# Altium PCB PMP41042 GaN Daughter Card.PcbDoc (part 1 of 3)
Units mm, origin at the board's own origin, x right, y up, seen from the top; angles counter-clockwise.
Board outline 43.43 x 37.33 mm, 6 copper layers (Top Layer, MidLayer1, MidLayer2, MidLayer3, MidLayer4, Bottom Layer), stack 1.844 mm thick; 57 components, 55 nets, 240 pads, 238 vias.
Unrouted connection lines stored in the file: 15.
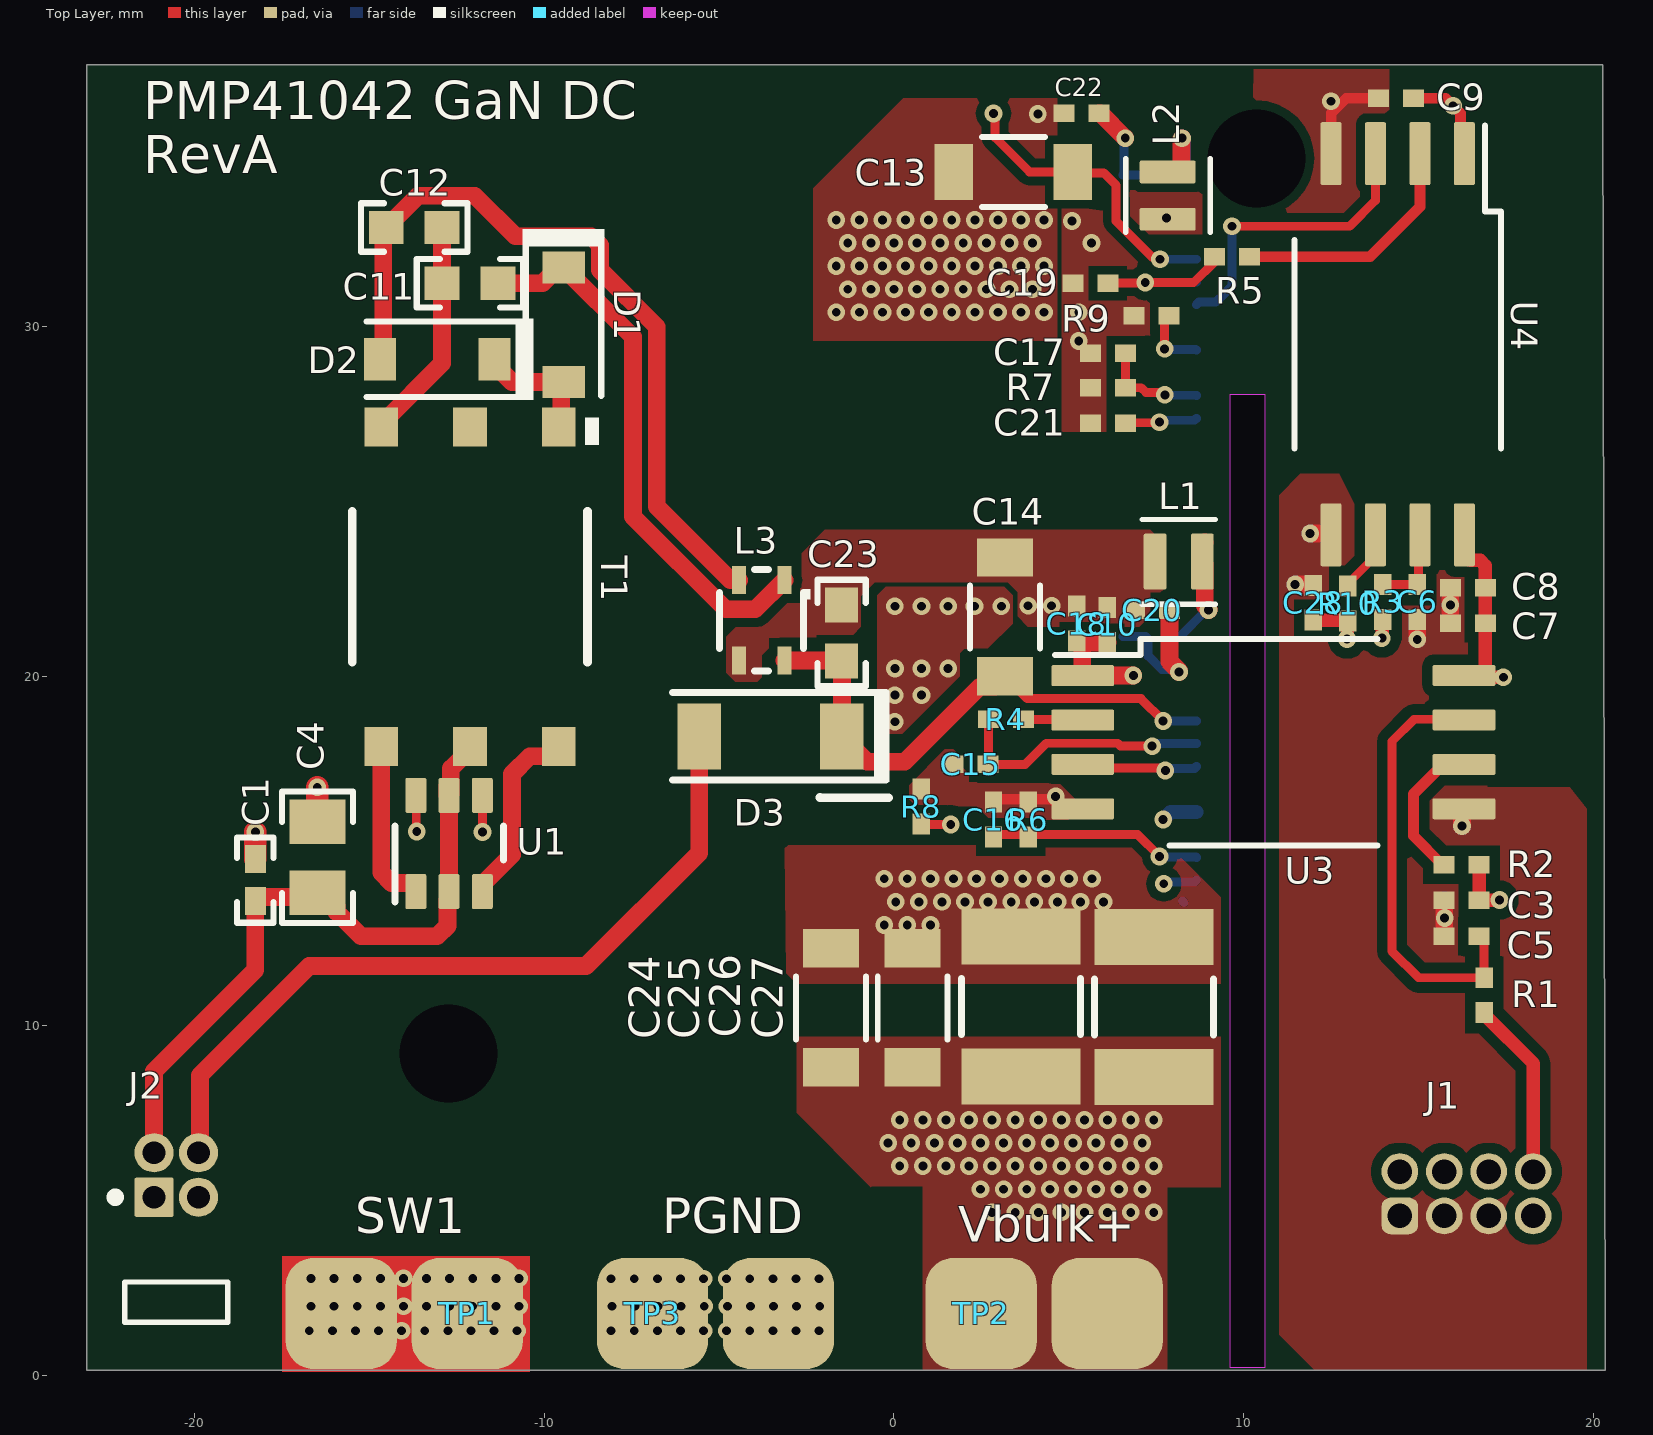
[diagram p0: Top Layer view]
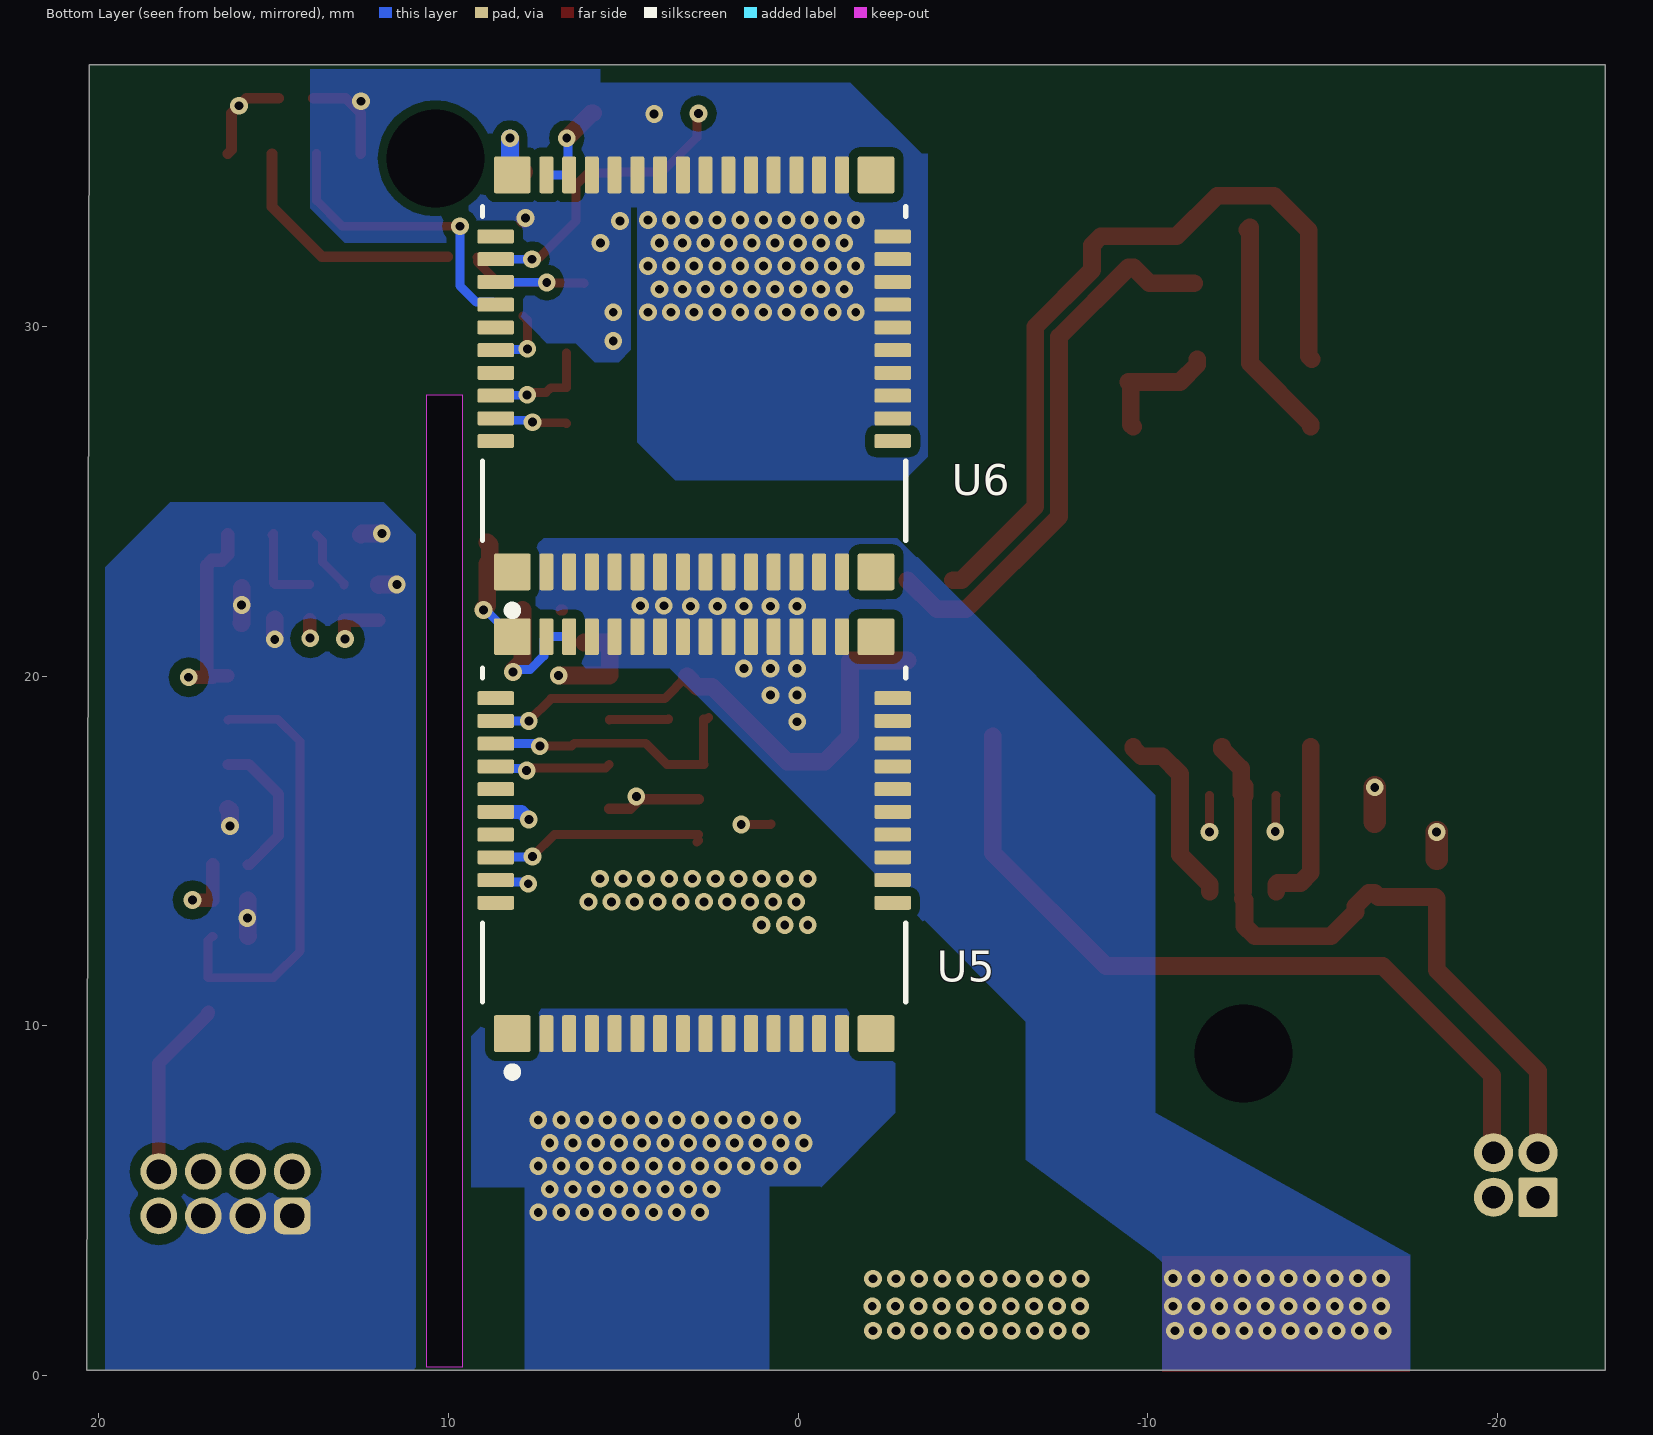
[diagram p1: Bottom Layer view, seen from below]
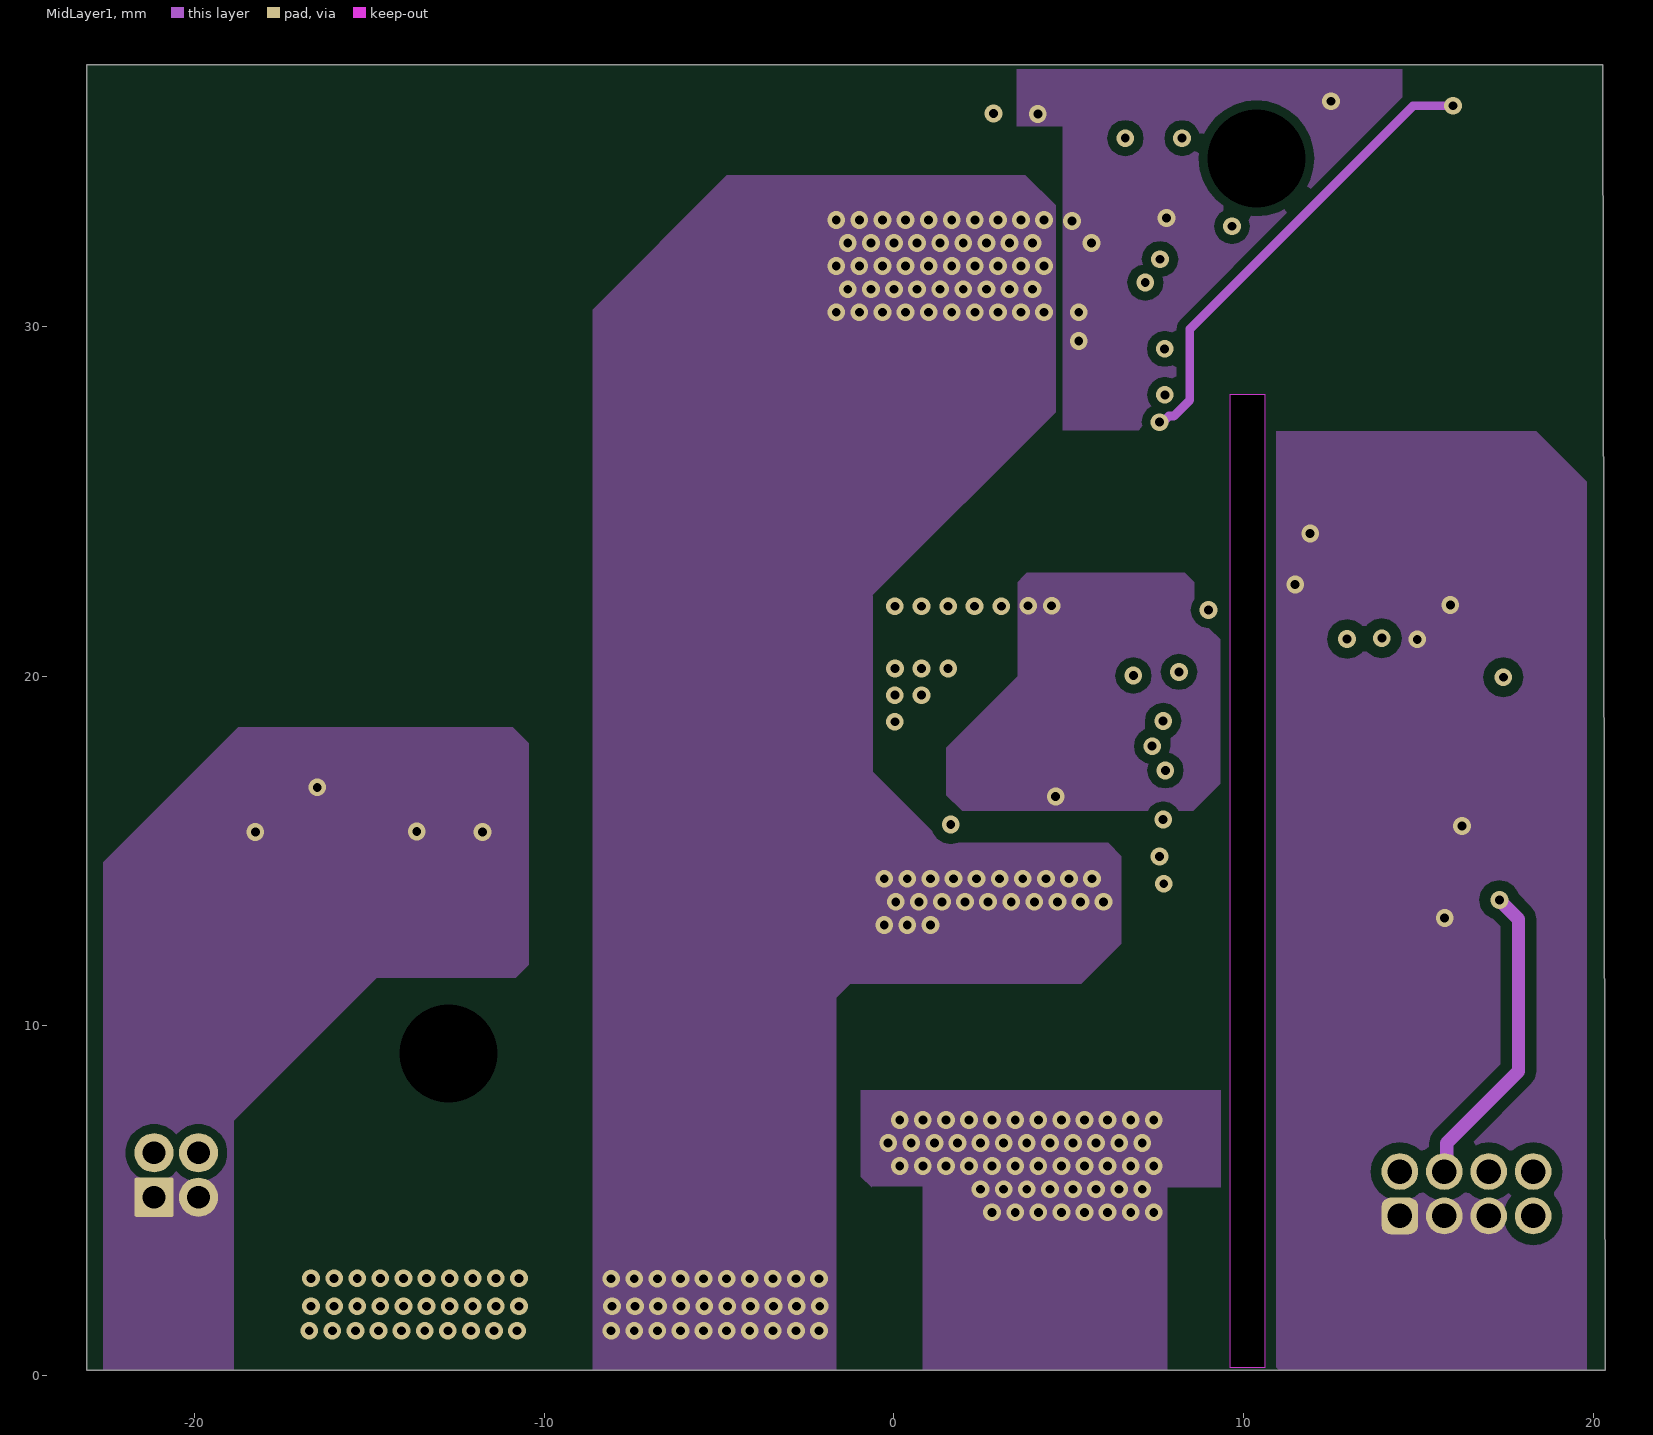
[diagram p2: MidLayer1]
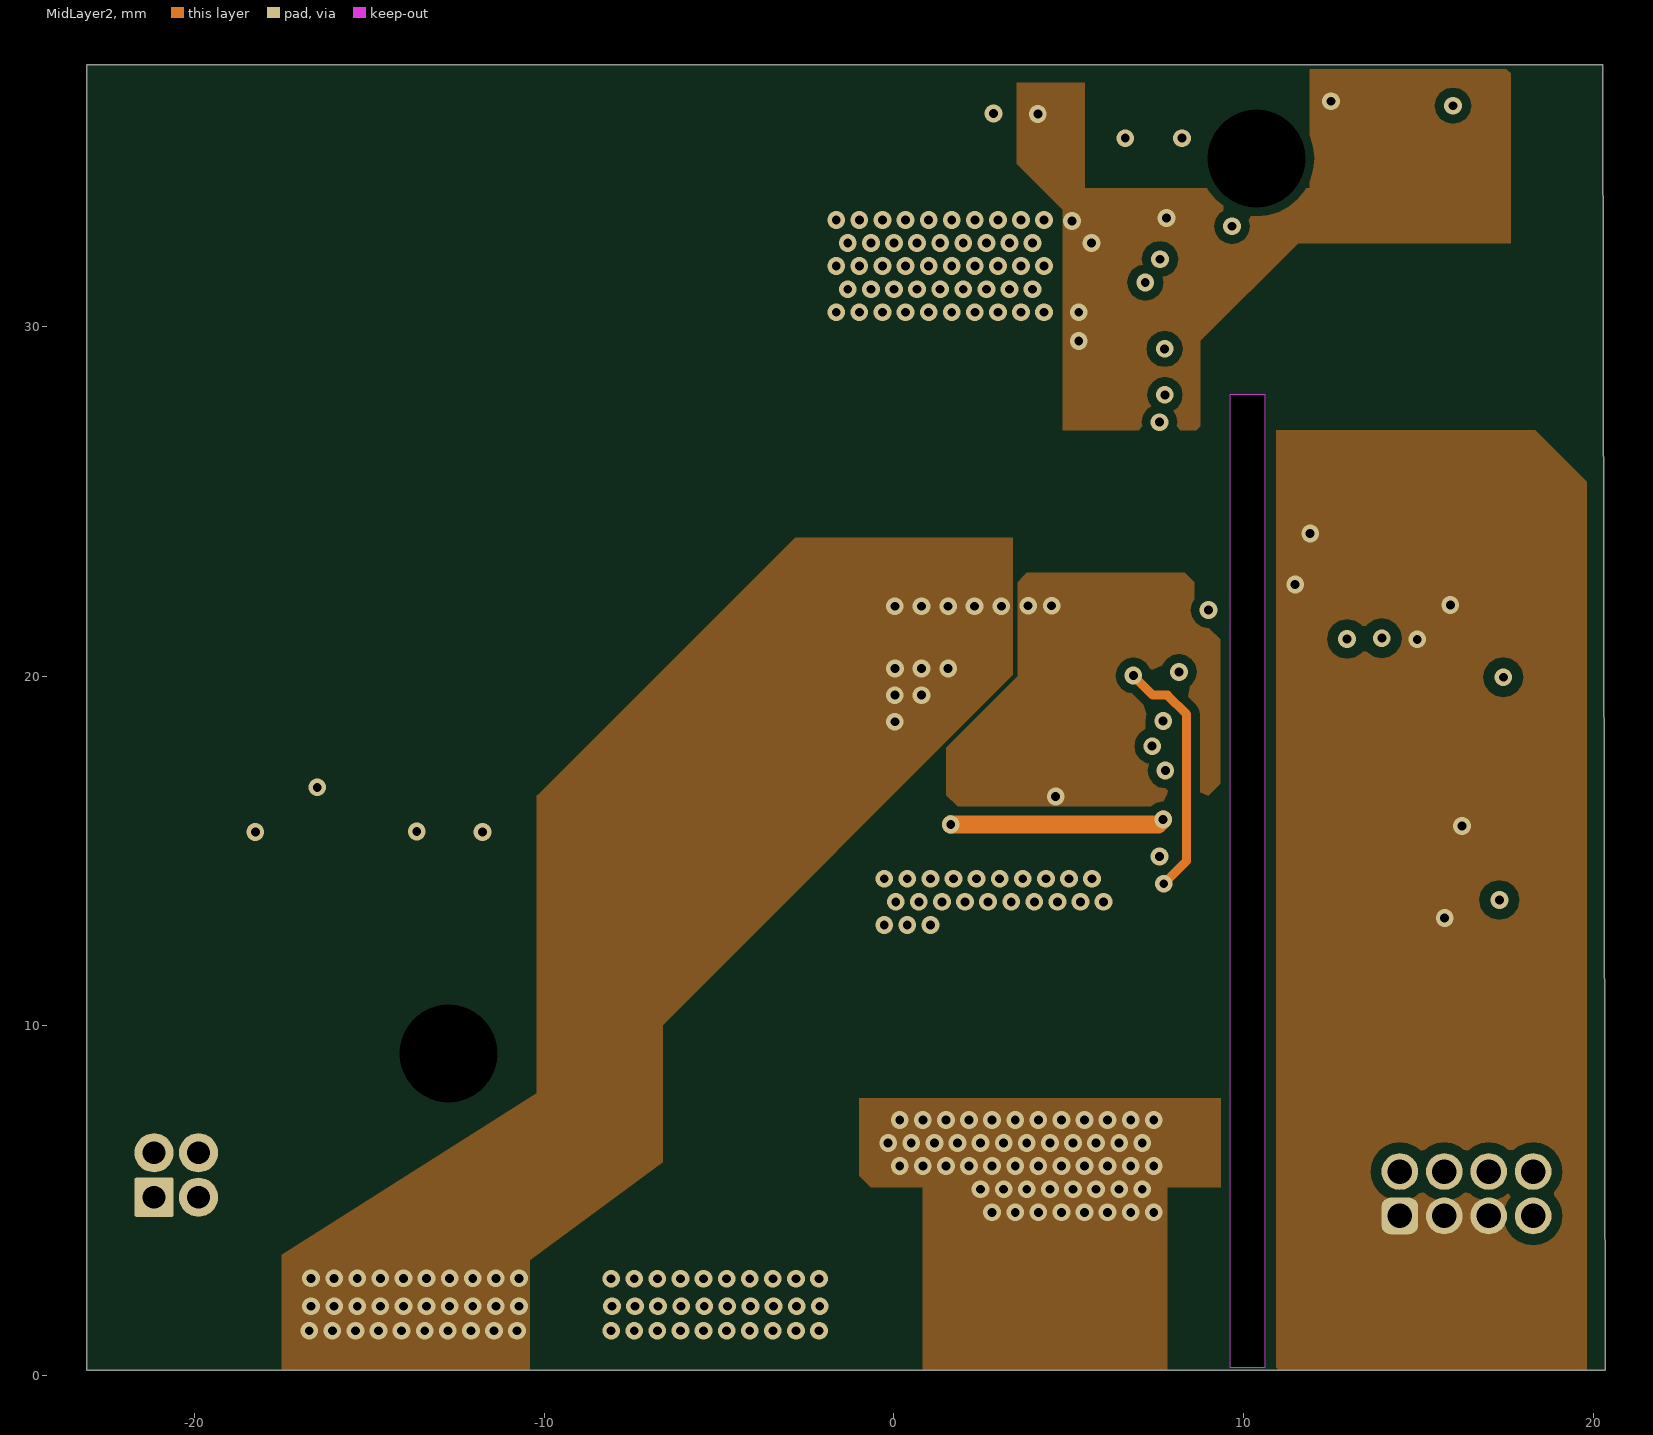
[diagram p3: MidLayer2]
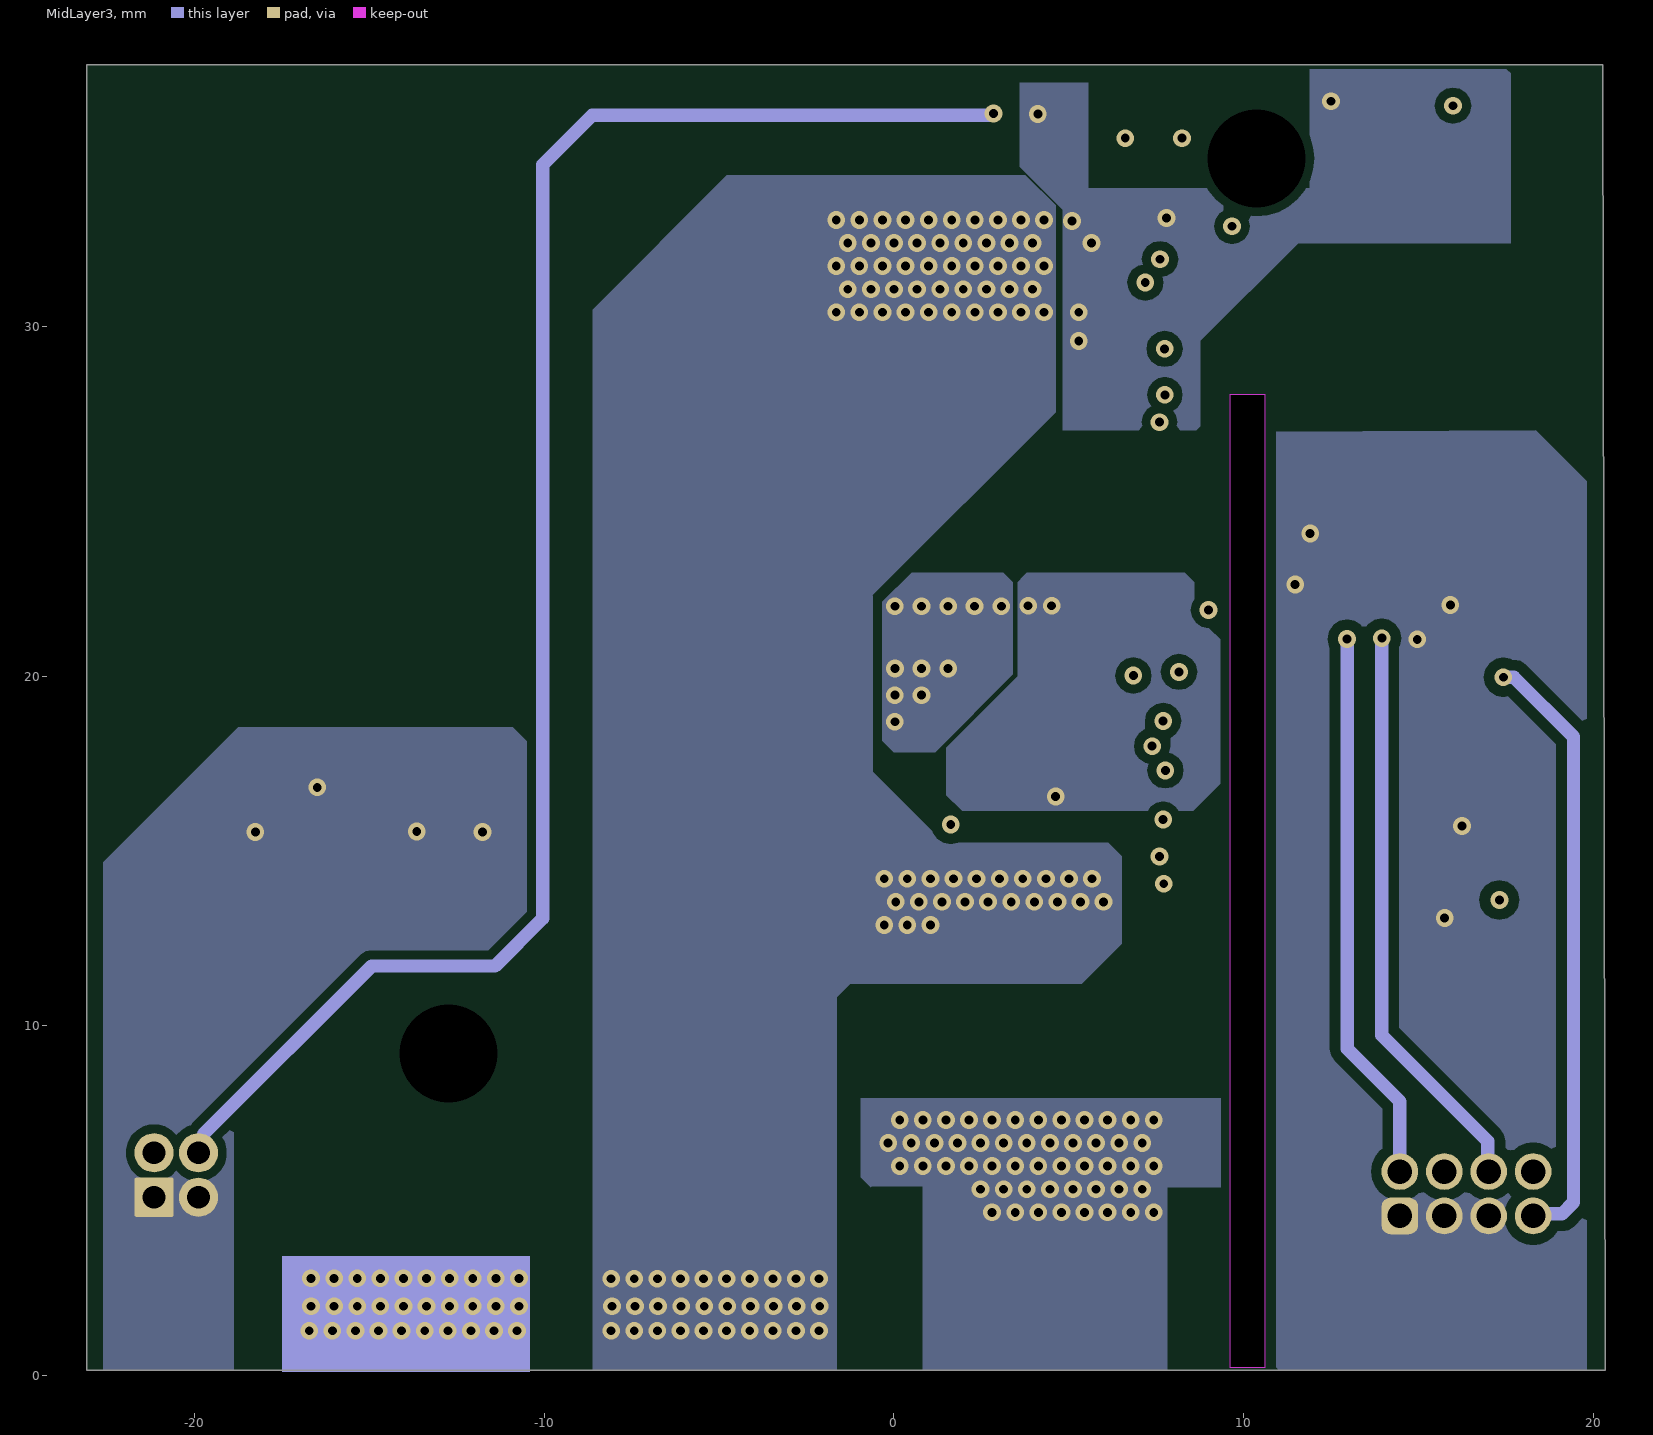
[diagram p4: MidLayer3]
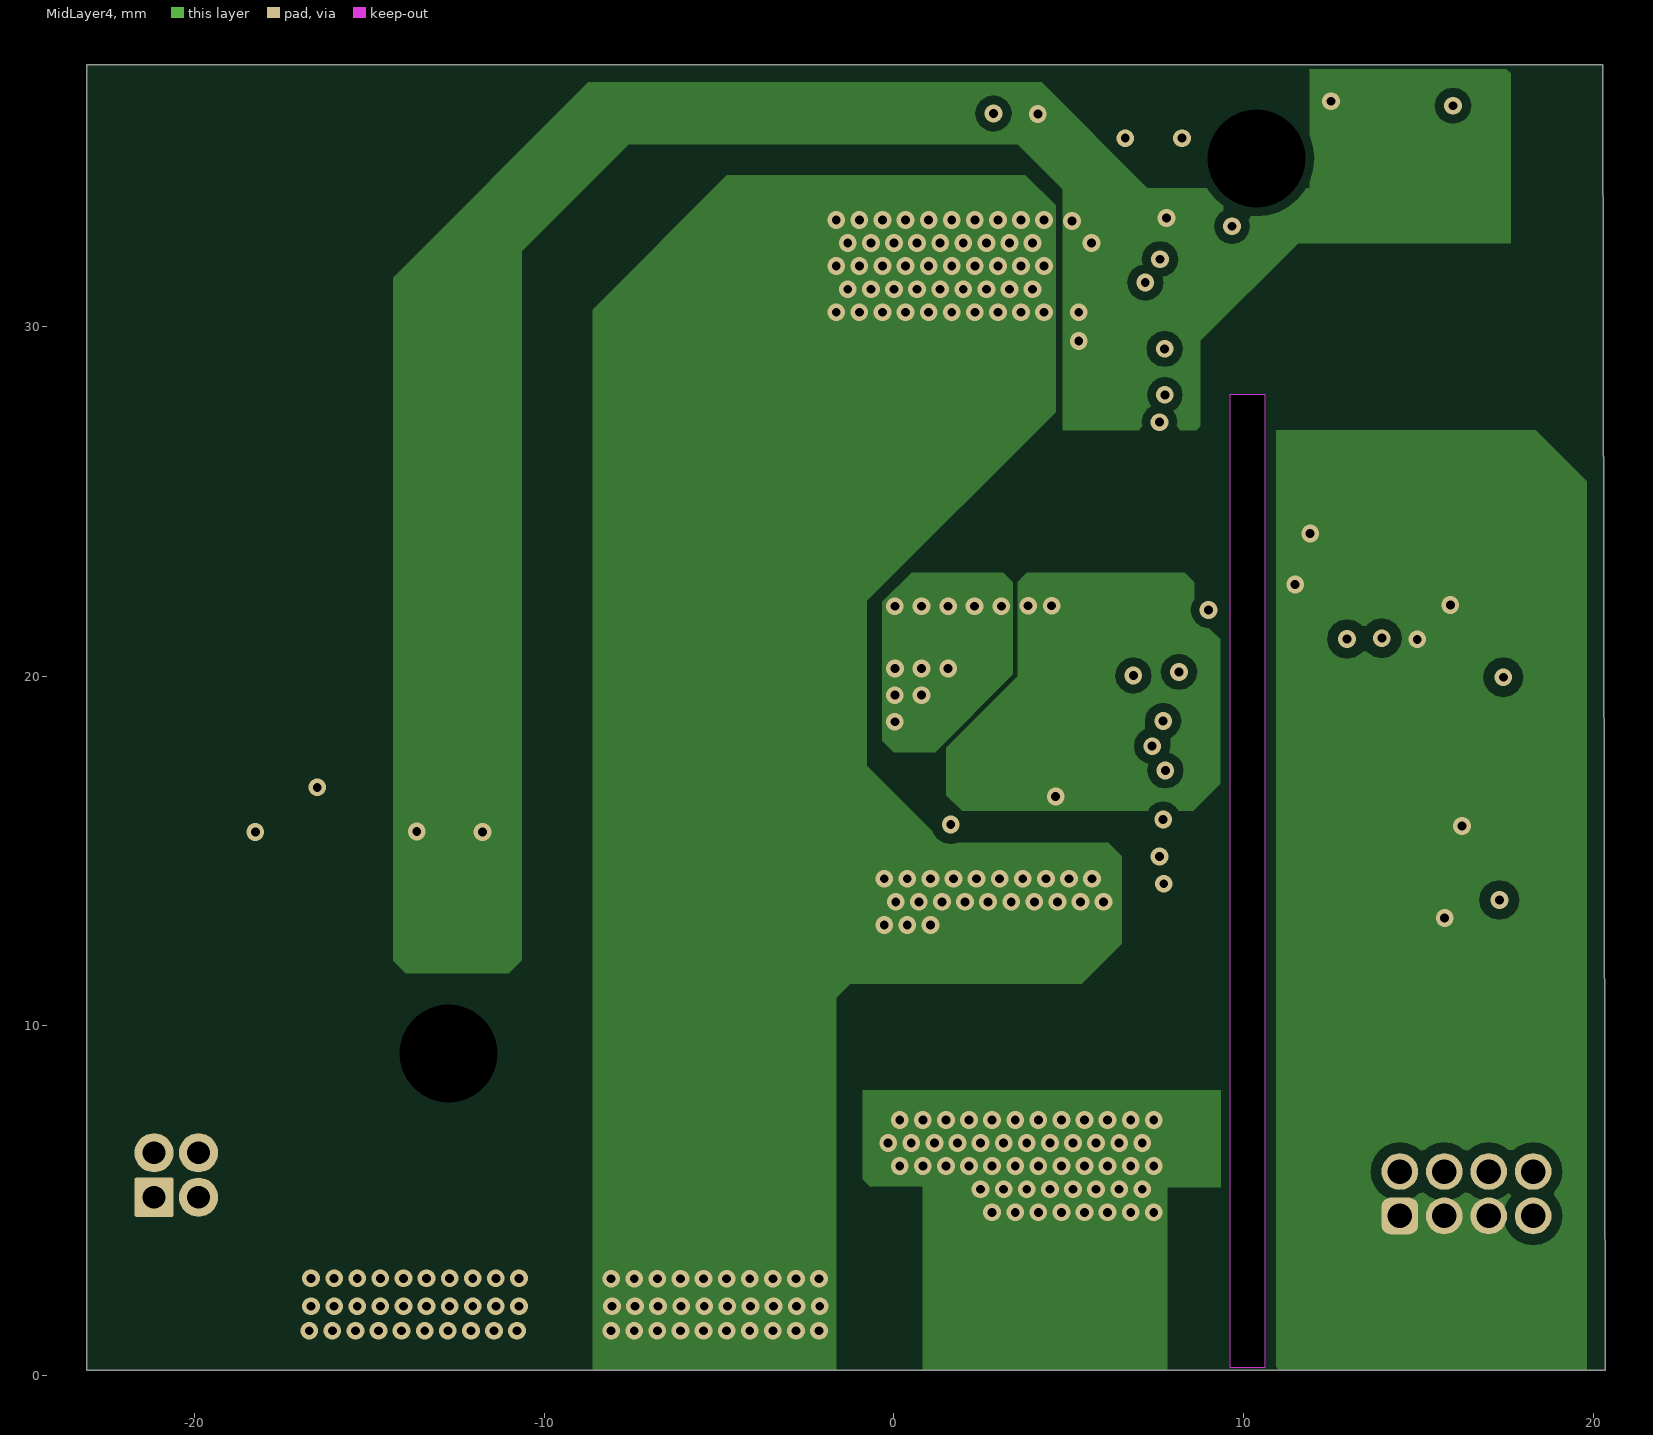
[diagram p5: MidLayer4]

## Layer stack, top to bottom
Top Solder: solder mask 0.0102, Solder Resist, Dk 3.5
Top Layer: signal copper 0.0711
Dielectric 1: prepreg 0.1168, PP-016, Dk 4.4
MidLayer1: signal copper 0.0711
Dielectric 2: core 0.5334, Core-037, Dk 4.8
MidLayer2: signal copper 0.0711
Dielectric 3: prepreg 0.1168, PP-016, Dk 4.4
MidLayer3: signal copper 0.0711
Dielectric 4: core 0.5334, Core-037, Dk 4.8
MidLayer4: signal copper 0.0711
Dielectric 5: prepreg 0.1168, PP-016, Dk 4.4
Bottom Layer: signal copper 0.0711
Bottom Solder: solder mask 0.0102, Solder Resist, Dk 3.5

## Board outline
-23.084,0.153 20.346,0.152 20.27,37.487 -23.084,37.487
cut-out: 10.622,0.239 10.622,28.042 9.606,28.042 9.606,0.239

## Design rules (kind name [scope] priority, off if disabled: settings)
AcuteAngle [All] p1: minimum=4.50000000000000E+0001 checktracksonly=FALSE
AssemblyTestPointUsage [All] p1: valid=2
BoardOutlineClearance BoardOutlineClearance_MountingHoles [OnCopper and InComponentClass('Mounting Holes')] p1: gap=1.016 ignorepadtopadclearanceinfootprint=FALSE
BoardOutlineClearance BoardOutlineClearance_Poly [OnCopper and IsPoly] p2: gap=0 ignorepadtopadclearanceinfootprint=FALSE
BoardOutlineClearance [OnCopper and Not InComponentClass('Logo') and not InComponentClass('FiducialMark') and not InRegion(1000,500,4000,800) and not InPoly] p3: gap=0 ignorepadtopadclearanceinfootprint=FALSE
Clearance Clearance_4 [InNet('AGND')] p1: gap=0.305 ignorepadtopadclearanceinfootprint=FALSE except(0.178: THPad-THPad; 0.254: Arc-Via Track-Via SMDPad-SMDPad)
Clearance Clearance_3 [InNamedPolygon('BOTTOM_LAYER_54V1_P128')] p2: gap=0.254 ignorepadtopadclearanceinfootprint=TRUE except(0: Arc-Hole Track-Hole SMDPad-Hole THPad-Hole Via-Hole Fill-Hole Poly-Hole Region-Hole Text-Hole)
Clearance Clearance_2 [InNetClass('AC') vs Not InNetClass('AC')] p3: gap=1.27 ignorepadtopadclearanceinfootprint=TRUE
Clearance Clearance_1 [InNetClass('HV') vs Not InNetClass('HV')] p4: gap=1.016 ignorepadtopadclearanceinfootprint=TRUE
Clearance Clearance_Keepouts [((IsTrack Or IsArc) And Not InPoly) And IsFree and IsKeepOut vs ((IsTrack Or IsArc) And Not InPoly) And IsFree and IsKeepOut] p5: gap=0 ignorepadtopadclearanceinfootprint=TRUE
Clearance Clearance_Poly [InPolygon] p6: gap=0.254 ignorepadtopadclearanceinfootprint=TRUE
Clearance Clearance_FiducialMark [IsKeepOut and InComponentClass('FiducialMark') vs IsPad and InComponentClass('FiducialMark')] p7: gap=0 ignorepadtopadclearanceinfootprint=FALSE
Clearance [All] p8: gap=0.178 ignorepadtopadclearanceinfootprint=TRUE except(0.15: SMDPad-SMDPad SMDPad-THPad THPad-THPad)
ComponentClearance ComponentClearance_MountingHoles_FiducialMarks [InComponentClass('Mounting Holes') vs InComponentClass('FiducialMark')] p1: gap=1.27 collisioncheckmode=3 verticalgap=0.254 showdistances=FALSE
ComponentClearance ComponentClearance_Shunt [InComponentClass('Header') vs InComponentClass('Shunt')] p2: gap=0 collisioncheckmode=3 verticalgap=0 showdistances=FALSE
ComponentClearance ComponentClearance_Logo [InComponentClass('Logo')] p3: gap=0.254 collisioncheckmode=3 verticalgap=0.254 showdistances=FALSE
ComponentClearance ComponentClearance_ScrewToNut [(HasFootprint('NY PMS 440 0025 PH')) vs (HasFootprint('Keystone_1902C'))] p4: gap=0.127 collisioncheckmode=3 verticalgap=0.254 showdistances=FALSE
ComponentClearance ComponentClearance_MountingHoles [InComponentClass('Mounting Holes')] p5: gap=1.27 collisioncheckmode=3 verticalgap=2540 showdistances=FALSE
ComponentClearance ComponentClearance_SmallPassives [HasFootprint('0201*') or HasFootprint('0402*') or HasFootprint('0508') or HasFootprint('0603*') or HasFootprint('0612') or HasFootprint('0805*') or HasFootprint('0815*') or HasFootprint('0830*') or HasFootprint('1206*') or HasFootprint('1210*') or HasFootprint('1808*') or HasFootprint('1812*') or HasFootprint('1825*') or HasFootprint('2010*') or HasFootprint('2220*') or HasFootprint('2225*') or HasFootprint('2512*') or HasFootprint('2728*') or HasFootprint('3518*') vs HasFootprint('0201*') or HasFootprint('0402*') or HasFootprint('0508') or HasFootprint('0603*') or HasFootprint('0612') or HasFootprint('0805*') or HasFootprint('0815*') or HasFootprint('0830*') or HasFootprint('1206*') or HasFootprint('1210*') or HasFootprint('1808*') or HasFootprint('1812*') or HasFootprint('1825*') or HasFootprint('2010*') or HasFootprint('2220*') or HasFootprint('2225*') or HasFootprint('2512*') or HasFootprint('2728*') or HasFootprint('3518*')] p6: gap=0.254 collisioncheckmode=3 verticalgap=0.254 showdistances=FALSE
ComponentClearance ComponentClearance_THtoSMT [IsThruComponent vs IsSMTComponent] p7: gap=0.254 collisioncheckmode=3 verticalgap=0.254 showdistances=FALSE
ComponentClearance ComponentClearance_THtoTH [IsThruComponent vs IsThruComponent] p8: gap=0.254 collisioncheckmode=3 verticalgap=0.254 showdistances=FALSE
ComponentClearance [All] p9: gap=0.254 collisioncheckmode=3 verticalgap=0.254 showdistances=FALSE
DiffPairsRouting [All] p1: maxlimit=2.54 minlimit=0.254 mostfreqgap=0.254 substack1={A02F224D-4808-492E-A71F-5F5656FBF0D4} toplayer_{a02f224d-4808-492e-a71f-5f5656fbf0d4}_minwidth=0.381 toplayer_{a02f224d-4808-492e-a71f-5f5656fbf0d4}_maxwidth=0.381 toplayer_{a02f224d-4808-492e-a71f-5f5656fbf0d4}_prefwidth=0.381 midlayer1_{a02f224d-4808-492e-a71f-5f5656fbf0d4}_minwidth=0.381 midlayer1_{a02f224d-4808-492e-a71f-5f5656fbf0d4}_maxwidth=0.381 midlayer1_{a02f224d-4808-492e-a71f-5f5656fbf0d4}_prefwidth=0.381 midlayer2_{a02f224d-4808-492e-a71f-5f5656fbf0d4}_minwidth=0.381 midlayer2_{a02f224d-4808-492e-a71f-5f5656fbf0d4}_maxwidth=0.381 midlayer2_{a02f224d-4808-492e-a71f-5f5656fbf0d4}_prefwidth=0.381 midlayer3_{a02f224d-4808-492e-a71f-5f5656fbf0d4}_minwidth=0.381 midlayer3_{a02f224d-4808-492e-a71f-5f5656fbf0d4}_maxwidth=0.381 midlayer3_{a02f224d-4808-492e-a71f-5f5656fbf0d4}_prefwidth=0.381 midlayer4_{a02f224d-4808-492e-a71f-5f5656fbf0d4}_minwidth=0.381 midlayer4_{a02f224d-4808-492e-a71f-5f5656fbf0d4}_maxwidth=0.381 midlayer4_{a02f224d-4808-492e-a71f-5f5656fbf0d4}_prefwidth=0.381 bottomlayer_{a02f224d-4808-492e-a71f-5f5656fbf0d4}_minwidth=0.381 bottomlayer_{a02f224d-4808-492e-a71f-5f5656fbf0d4}_maxwidth=0.381 bottomlayer_{a02f224d-4808-492e-a71f-5f5656fbf0d4}_prefwidth=0.381 substack2={B838D286-A00B-4EE2-88E1-F79279CC64B4} toplayer_{b838d286-a00b-4ee2-88e1-f79279cc64b4}_minwidth=0.381 toplayer_{b838d286-a00b-4ee2-88e1-f79279cc64b4}_maxwidth=0.381 toplayer_{b838d286-a00b-4ee2-88e1-f79279cc64b4}_prefwidth=0.381 midlayer1_{b838d286-a00b-4ee2-88e1-f79279cc64b4}_minwidth=0.381 midlayer1_{b838d286-a00b-4ee2-88e1-f79279cc64b4}_maxwidth=0.381 midlayer1_{b838d286-a00b-4ee2-88e1-f79279cc64b4}_prefwidth=0.381 midlayer2_{b838d286-a00b-4ee2-88e1-f79279cc64b4}_minwidth=0.381 midlayer2_{b838d286-a00b-4ee2-88e1-f79279cc64b4}_maxwidth=0.381 midlayer2_{b838d286-a00b-4ee2-88e1-f79279cc64b4}_prefwidth=0.381 midlayer3_{b838d286-a00b-4ee2-88e1-f79279cc64b4}_minwidth=0.381 midlayer3_{b838d286-a00b-4ee2-88e1-f79279cc64b4}_maxwidth=0.381 midlayer3_{b838d286-a00b-4ee2-88e1-f79279cc64b4}_prefwidth=0.381 midlayer4_{b838d286-a00b-4ee2-88e1-f79279cc64b4}_minwidth=0.381 midlayer4_{b838d286-a00b-4ee2-88e1-f79279cc64b4}_maxwidth=0.381 midlayer4_{b838d286-a00b-4ee2-88e1-f79279cc64b4}_prefwidth=0.381 bottomlayer_{b838d286-a00b-4ee2-88e1-f79279cc64b4}_minwidth=0.381 bottomlayer_{b838d286-a00b-4ee2-88e1-f79279cc64b4}_maxwidth=0.381 bottomlayer_{b838d286-a00b-4ee2-88e1-f79279cc64b4}_prefwidth=0.381 substack3={0D253197-D122-4D2B-9584-B8C12AA3806F} toplayer_{0d253197-d122-4d2b-9584-b8c12aa3806f}_minwidth=0.381 toplayer_{0d253197-d122-4d2b-9584-b8c12aa3806f}_maxwidth=0.381 toplayer_{0d253197-d122-4d2b-9584-b8c12aa3806f}_prefwidth=0.381 midlayer1_{0d253197-d122-4d2b-9584-b8c12aa3806f}_minwidth=0.381 midlayer1_{0d253197-d122-4d2b-9584-b8c12aa3806f}_maxwidth=0.381 midlayer1_{0d253197-d122-4d2b-9584-b8c12aa3806f}_prefwidth=0.381 midlayer2_{0d253197-d122-4d2b-9584-b8c12aa3806f}_minwidth=0.381 midlayer2_{0d253197-d122-4d2b-9584-b8c12aa3806f}_maxwidth=0.381 midlayer2_{0d253197-d122-4d2b-9584-b8c12aa3806f}_prefwidth=0.381 midlayer3_{0d253197-d122-4d2b-9584-b8c12aa3806f}_minwidth=0.381 midlayer3_{0d253197-d122-4d2b-9584-b8c12aa3806f}_maxwidth=0.381 midlayer3_{0d253197-d122-4d2b-9584-b8c12aa3806f}_prefwidth=0.381 midlayer4_{0d253197-d122-4d2b-9584-b8c12aa3806f}_minwidth=0.381 midlayer4_{0d253197-d122-4d2b-9584-b8c12aa3806f}_maxwidth=0.381 midlayer4_{0d253197-d122-4d2b-9584-b8c12aa3806f}_prefwidth=0.381 bottomlayer_{0d253197-d122-4d2b-9584-b8c12aa3806f}_minwidth=0.381 bottomlayer_{0d253197-d122-4d2b-9584-b8c12aa3806f}_maxwidth=0.381 bottomlayer_{0d253197-d122-4d2b-9584-b8c12aa3806f}_prefwidth=0.381 substack4={88BCB183-C685-456E-B90A-365A53404C2C} toplayer_{88bcb183-c685-456e-b90a-365a53404c2c}_minwidth=0.381 toplayer_{88bcb183-c685-456e-b90a-365a53404c2c}_maxwidth=0.381 toplayer_{88bcb183-c685-456e-b90a-365a53404c2c}_prefwidth=0.381 midlayer1_{88bcb183-c685-456e-b90a-365a53404c2c}_minwidth=0.381 midlayer1_{88bcb183-c685-456e-b90a-365a53404c2c}_maxwidth=0.381 midlayer1_{88bcb183-c685-456e-b90a-365a53404c2c}_prefwidth=0.381 midlayer2_{88bcb183-c685-456e-b90a-365a53404c2c}_minwidth=0.381 midlayer2_{88bcb183-c685-456e-b90a-365a53404c2c}_maxwidth=0.381 midlayer2_{88bcb183-c685-456e-b90a-365a53404c2c}_prefwidth=0.381 midlayer3_{88bcb183-c685-456e-b90a-365a53404c2c}_minwidth=0.381 midlayer3_{88bcb183-c685-456e-b90a-365a53404c2c}_maxwidth=0.381 midlayer3_{88bcb183-c685-456e-b90a-365a53404c2c}_prefwidth=0.381 midlayer4_{88bcb183-c685-456e-b90a-365a53404c2c}_minwidth=0.381 midlayer4_{88bcb183-c685-456e-b90a-365a53404c2c}_maxwidth=0.381 midlayer4_{88bcb183-c685-456e-b90a-365a53404c2c}_prefwidth=0.381 bottomlayer_{88bcb183-c685-456e-b90a-365a53404c2c}_minwidth=0.381 bottomlayer_{88bcb183-c685-456e-b90a-365a53404c2c}_maxwidth=0.381 bottomlayer_{88bcb183-c685-456e-b90a-365a53404c2c}_prefwidth=0.381 substack5={4C8C2325-90D5-40B8-8B6B-4F66D44EFE25} toplayer_{4c8c2325-90d5-40b8-8b6b-4f66d44efe25}_minwidth=0.381 toplayer_{4c8c2325-90d5-40b8-8b6b-4f66d44efe25}_maxwidth=0.381 toplayer_{4c8c2325-90d5-40b8-8b6b-4f66d44efe25}_prefwidth=0.381 midlayer1_{4c8c2325-90d5-40b8-8b6b-4f66d44efe25}_minwidth=0.381 midlayer1_{4c8c2325-90d5-40b8-8b6b-4f66d44efe25}_maxwidth=0.381 midlayer1_{4c8c2325-90d5-40b8-8b6b-4f66d44efe25}_prefwidth=0.381 midlayer2_{4c8c2325-90d5-40b8-8b6b-4f66d44efe25}_minwidth=0.381 midlayer2_{4c8c2325-90d5-40b8-8b6b-4f66d44efe25}_maxwidth=0.381 midlayer2_{4c8c2325-90d5-40b8-8b6b-4f66d44efe25}_prefwidth=0.381 midlayer3_{4c8c2325-90d5-40b8-8b6b-4f66d44efe25}_minwidth=0.381 midlayer3_{4c8c2325-90d5-40b8-8b6b-4f66d44efe25}_maxwidth=0.381 midlayer3_{4c8c2325-90d5-40b8-8b6b-4f66d44efe25}_prefwidth=0.381 midlayer4_{4c8c2325-90d5-40b8-8b6b-4f66d44efe25}_minwidth=0.381 midlayer4_{4c8c2325-90d5-40b8-8b6b-4f66d44efe25}_maxwidth=0.381 midlayer4_{4c8c2325-90d5-40b8-8b6b-4f66d44efe25}_prefwidth=0.381 bottomlayer_{4c8c2325-90d5-40b8-8b6b-4f66d44efe25}_minwidth=0.381 bottomlayer_{4c8c2325-90d5-40b8-8b6b-4f66d44efe25}_maxwidth=0.381 bottomlayer_{4c8c2325-90d5-40b8-8b6b-4f66d44efe25}_prefwidth=0.381 toplayer_minwidth=0.381 toplayer_maxwidth=0.381 toplayer_prefwidth=0.381 midlayer1_minwidth=0.381 midlayer1_maxwidth=0.381 midlayer1_prefwidth=0.381 midlayer2_minwidth=0.381 midlayer2_maxwidth=0.381 midlayer2_prefwidth=0.381 midlayer3_minwidth=0.381 midlayer3_maxwidth=0.381 midlayer3_prefwidth=0.381 midlayer4_minwidth=0.381 midlayer4_maxwidth=0.381 midlayer4_prefwidth=0.381 bottomlayer_minwidth=0.381 bottomlayer_maxwidth=0.381 bottomlayer_prefwidth=0.381 substack6={553D66F5-99EF-40B1-BA7C-73E3B04B176F} toplayer_{553d66f5-99ef-40b1-ba7c-73e3b04b176f}_minwidth=0.381 toplayer_{553d66f5-99ef-40b1-ba7c-73e3b04b176f}_maxwidth=0.381 toplayer_{553d66f5-99ef-40b1-ba7c-73e3b04b176f}_prefwidth=0.381 midlayer1_{553d66f5-99ef-40b1-ba7c-73e3b04b176f}_minwidth=0.381 midlayer1_{553d66f5-99ef-40b1-ba7c-73e3b04b176f}_maxwidth=0.381 midlayer1_{553d66f5-99ef-40b1-ba7c-73e3b04b176f}_prefwidth=0.381 midlayer2_{553d66f5-99ef-40b1-ba7c-73e3b04b176f}_minwidth=0.381 midlayer2_{553d66f5-99ef-40b1-ba7c-73e3b04b176f}_maxwidth=0.381 midlayer2_{553d66f5-99ef-40b1-ba7c-73e3b04b176f}_prefwidth=0.381 midlayer3_{553d66f5-99ef-40b1-ba7c-73e3b04b176f}_minwidth=0.381 midlayer3_{553d66f5-99ef-40b1-ba7c-73e3b04b176f}_maxwidth=0.381 midlayer3_{553d66f5-99ef-40b1-ba7c-73e3b04b176f}_prefwidth=0.381 midlayer4_{553d66f5-99ef-40b1-ba7c-73e3b04b176f}_minwidth=0.381 midlayer4_{553d66f5-99ef-40b1-ba7c-73e3b04b176f}_maxwidth=0.381 midlayer4_{553d66f5-99ef-40b1-ba7c-73e3b04b176f}_prefwidth=0.381 bottomlayer_{553d66f5-99ef-40b1-ba7c-73e3b04b176f}_minwidth=0.381 bottomlayer_{553d66f5-99ef-40b1-ba7c-73e3b04b176f}_maxwidth=0.381 bottomlayer_{553d66f5-99ef-40b1-ba7c-73e3b04b176f}_prefwidth=0.381 substack7={FF0C9878-5A48-402E-B013-8E2EEFCEDCCB} toplayer_{ff0c9878-5a48-402e-b013-8e2eefcedccb}_minwidth=0.381 toplayer_{ff0c9878-5a48-402e-b013-8e2eefcedccb}_maxwidth=0.381 toplayer_{ff0c9878-5a48-402e-b013-8e2eefcedccb}_prefwidth=0.381 midlayer1_{ff0c9878-5a48-402e-b013-8e2eefcedccb}_minwidth=0.381 midlayer1_{ff0c9878-5a48-402e-b013-8e2eefcedccb}_maxwidth=0.381 midlayer1_{ff0c9878-5a48-402e-b013-8e2eefcedccb}_prefwidth=0.381 midlayer2_{ff0c9878-5a48-402e-b013-8e2eefcedccb}_minwidth=0.381 midlayer2_{ff0c9878-5a48-402e-b013-8e2eefcedccb}_maxwidth=0.381 midlayer2_{ff0c9878-5a48-402e-b013-8e2eefcedccb}_prefwidth=0.381 midlayer3_{ff0c9878-5a48-402e-b013-8e2eefcedccb}_minwidth=0.381 midlayer3_{ff0c9878-5a48-402e-b013-8e2eefcedccb}_maxwidth=0.381 midlayer3_{ff0c9878-5a48-402e-b013-8e2eefcedccb}_prefwidth=0.381 midlayer4_{ff0c9878-5a48-402e-b013-8e2eefcedccb}_minwidth=0.381 midlayer4_{ff0c9878-5a48-402e-b013-8e2eefcedccb}_maxwidth=0.381 midlayer4_{ff0c9878-5a48-402e-b013-8e2eefcedccb}_prefwidth=0.381 bottomlayer_{ff0c9878-5a48-402e-b013-8e2eefcedccb}_minwidth=0.381 bottomlayer_{ff0c9878-5a48-402e-b013-8e2eefcedccb}_maxwidth=0.381 bottomlayer_{ff0c9878-5a48-402e-b013-8e2eefcedccb}_prefwidth=0.381 substack8={5BB5B65B-6C7F-4868-A6AE-66DD57ADDCBD} toplayer_{5bb5b65b-6c7f-4868-a6ae-66dd57addcbd}_minwidth=0.381 toplayer_{5bb5b65b-6c7f-4868-a6ae-66dd57addcbd}_maxwidth=0.381 toplayer_{5bb5b65b-6c7f-4868-a6ae-66dd57addcbd}_prefwidth=0.381 midlayer1_{5bb5b65b-6c7f-4868-a6ae-66dd57addcbd}_minwidth=0.381 midlayer1_{5bb5b65b-6c7f-4868-a6ae-66dd57addcbd}_maxwidth=0.381 midlayer1_{5bb5b65b-6c7f-4868-a6ae-66dd57addcbd}_prefwidth=0.381 midlayer2_{5bb5b65b-6c7f-4868-a6ae-66dd57addcbd}_minwidth=0.381 midlayer2_{5bb5b65b-6c7f-4868-a6ae-66dd57addcbd}_maxwidth=0.381 midlayer2_{5bb5b65b-6c7f-4868-a6ae-66dd57addcbd}_prefwidth=0.381 midlayer3_{5bb5b65b-6c7f-4868-a6ae-66dd57addcbd}_minwidth=0.381 midlayer3_{5bb5b65b-6c7f-4868-a6ae-66dd57addcbd}_maxwidth=0.381 midlayer3_{5bb5b65b-6c7f-4868-a6ae-66dd57addcbd}_prefwidth=0.381 midlayer4_{5bb5b65b-6c7f-4868-a6ae-66dd57addcbd}_minwidth=0.381 midlayer4_{5bb5b65b-6c7f-4868-a6ae-66dd57addcbd}_maxwidth=0.381 midlayer4_{5bb5b65b-6c7f-4868-a6ae-66dd57addcbd}_prefwidth=0.381 bottomlayer_{5bb5b65b-6c7f-4868-a6ae-66dd57addcbd}_minwidth=0.381 bottomlayer_{5bb5b65b-6c7f-4868-a6ae-66dd57addcbd}_maxwidth=0.381 bottomlayer_{5bb5b65b-6c7f-4868-a6ae-66dd57addcbd}_prefwidth=0.381 substack9={65866CD6-1929-42AF-BAA8-019D5E6BA212} toplayer_{65866cd6-1929-42af-baa8-019d5e6ba212}_minwidth=0.381 toplayer_{65866cd6-1929-42af-baa8-019d5e6ba212}_maxwidth=0.381 toplayer_{65866cd6-1929-42af-baa8-019d5e6ba212}_prefwidth=0.381 midlayer1_{65866cd6-1929-42af-baa8-019d5e6ba212}_minwidth=0.381 midlayer1_{65866cd6-1929-42af-baa8-019d5e6ba212}_maxwidth=0.381 midlayer1_{65866cd6-1929-42af-baa8-019d5e6ba212}_prefwidth=0.381 midlayer2_{65866cd6-1929-42af-baa8-019d5e6ba212}_minwidth=0.381 midlayer2_{65866cd6-1929-42af-baa8-019d5e6ba212}_maxwidth=0.381 midlayer2_{65866cd6-1929-42af-baa8-019d5e6ba212}_prefwidth=0.381 midlayer3_{65866cd6-1929-42af-baa8-019d5e6ba212}_minwidth=0.381 midlayer3_{65866cd6-1929-42af-baa8-019d5e6ba212}_maxwidth=0.381 midlayer3_{65866cd6-1929-42af-baa8-019d5e6ba212}_prefwidth=0.381 midlayer4_{65866cd6-1929-42af-baa8-019d5e6ba212}_minwidth=0.381 midlayer4_{65866cd6-1929-42af-baa8-019d5e6ba212}_maxwidth=0.381 midlayer4_{65866cd6-1929-42af-baa8-019d5e6ba212}_prefwidth=0.381 bottomlayer_{65866cd6-1929-42af-baa8-019d5e6ba212}_minwidth=0.381 bottomlayer_{65866cd6-1929-42af-baa8-019d5e6ba212}_maxwidth=0.381 bottomlayer_{65866cd6-1929-42af-baa8-019d5e6ba212}_prefwidth=0.381 substack10={590F0BEA-1E04-4904-B9C9-D9D160075BC2} toplayer_{590f0bea-1e04-4904-b9c9-d9d160075bc2}_minwidth=0.381 toplayer_{590f0bea-1e04-4904-b9c9-d9d160075bc2}_maxwidth=0.381 toplayer_{590f0bea-1e04-4904-b9c9-d9d160075bc2}_prefwidth=0.381 midlayer1_{590f0bea-1e04-4904-b9c9-d9d160075bc2}_minwidth=0.381 midlayer1_{590f0bea-1e04-4904-b9c9-d9d160075bc2}_maxwidth=0.381 midlayer1_{590f0bea-1e04-4904-b9c9-d9d160075bc2}_prefwidth=0.381 midlayer2_{590f0bea-1e04-4904-b9c9-d9d160075bc2}_minwidth=0.381 midlayer2_{590f0bea-1e04-4904-b9c9-d9d160075bc2}_maxwidth=0.381 midlayer2_{590f0bea-1e04-4904-b9c9-d9d160075bc2}_prefwidth=0.381 midlayer3_{590f0bea-1e04-4904-b9c9-d9d160075bc2}_minwidth=0.381 midlayer3_{590f0bea-1e04-4904-b9c9-d9d160075bc2}_maxwidth=0.381 midlayer3_{590f0bea-1e04-4904-b9c9-d9d160075bc2}_prefwidth=0.381 midlayer4_{590f0bea-1e04-4904-b9c9-d9d160075bc2}_minwidth=0.381 midlayer4_{590f0bea-1e04-4904-b9c9-d9d160075bc2}_maxwidth=0.381 midlayer4_{590f0bea-1e04-4904-b9c9-d9d160075bc2}_prefwidth=0.381 bottomlayer_{590f0bea-1e04-4904-b9c9-d9d160075bc2}_minwidth=0.381 bottomlayer_{590f0bea-1e04-4904-b9c9-d9d160075bc2}_maxwidth=0.381 bottomlayer_{590f0bea-1e04-4904-b9c9-d9d160075bc2}_prefwidth=0.381 substack11={B2AC4F48-1A5F-44D7-A91B-3BAADFDAAED0} toplayer_{b2ac4f48-1a5f-44d7-a91b-3baadfdaaed0}_minwidth=0.381 toplayer_{b2ac4f48-1a5f-44d7-a91b-3baadfdaaed0}_maxwidth=0.381 toplayer_{b2ac4f48-1a5f-44d7-a91b-3baadfdaaed0}_prefwidth=0.381 midlayer1_{b2ac4f48-1a5f-44d7-a91b-3baadfdaaed0}_minwidth=0.381 midlayer1_{b2ac4f48-1a5f-44d7-a91b-3baadfdaaed0}_maxwidth=0.381 midlayer1_{b2ac4f48-1a5f-44d7-a91b-3baadfdaaed0}_prefwidth=0.381 midlayer2_{b2ac4f48-1a5f-44d7-a91b-3baadfdaaed0}_minwidth=0.381 midlayer2_{b2ac4f48-1a5f-44d7-a91b-3baadfdaaed0}_maxwidth=0.381 midlayer2_{b2ac4f48-1a5f-44d7-a91b-3baadfdaaed0}_prefwidth=0.381 midlayer3_{b2ac4f48-1a5f-44d7-a91b-3baadfdaaed0}_minwidth=0.381 midlayer3_{b2ac4f48-1a5f-44d7-a91b-3baadfdaaed0}_maxwidth=0.381 midlayer3_{b2ac4f48-1a5f-44d7-a91b-3baadfdaaed0}_prefwidth=0.381 midlayer4_{b2ac4f48-1a5f-44d7-a91b-3baadfdaaed0}_minwidth=0.381 midlayer4_{b2ac4f48-1a5f-44d7-a91b-3baadfdaaed0}_maxwidth=0.381 midlayer4_{b2ac4f48-1a5f-44d7-a91b-3baadfdaaed0}_prefwidth=0.381 bottomlayer_{b2ac4f48-1a5f-44d7-a91b-3baadfdaaed0}_minwidth=0.381 bottomlayer_{b2ac4f48-1a5f-44d7-a91b-3baadfdaaed0}_maxwidth=0.381 bottomlayer_{b2ac4f48-1a5f-44d7-a91b-3baadfdaaed0}_prefwidth=0.381 substack12={DD3D4156-A54D-4E1F-B7FF-E5EF72C45496} toplayer_{dd3d4156-a54d-4e1f-b7ff-e5ef72c45496}_minwidth=0.381 toplayer_{dd3d4156-a54d-4e1f-b7ff-e5ef72c45496}_maxwidth=0.381 toplayer_{dd3d4156-a54d-4e1f-b7ff-e5ef72c45496}_prefwidth=0.381 midlayer1_{dd3d4156-a54d-4e1f-b7ff-e5ef72c45496}_minwidth=0.381 midlayer1_{dd3d4156-a54d-4e1f-b7ff-e5ef72c45496}_maxwidth=0.381 midlayer1_{dd3d4156-a54d-4e1f-b7ff-e5ef72c45496}_prefwidth=0.381 midlayer2_{dd3d4156-a54d-4e1f-b7ff-e5ef72c45496}_minwidth=0.381 midlayer2_{dd3d4156-a54d-4e1f-b7ff-e5ef72c45496}_maxwidth=0.381 midlayer2_{dd3d4156-a54d-4e1f-b7ff-e5ef72c45496}_prefwidth=0.381 midlayer3_{dd3d4156-a54d-4e1f-b7ff-e5ef72c45496}_minwidth=0.381 midlayer3_{dd3d4156-a54d-4e1f-b7ff-e5ef72c45496}_maxwidth=0.381 midlayer3_{dd3d4156-a54d-4e1f-b7ff-e5ef72c45496}_prefwidth=0.381 midlayer4_{dd3d4156-a54d-4e1f-b7ff-e5ef72c45496}_minwidth=0.381 midlayer4_{dd3d4156-a54d-4e1f-b7ff-e5ef72c45496}_maxwidth=0.381 midlayer4_{dd3d4156-a54d-4e1f-b7ff-e5ef72c45496}_prefwidth=0.381 bottomlayer_{dd3d4156-a54d-4e1f-b7ff-e5ef72c45496}_minwidth=0.381 bottomlayer_{dd3d4156-a54d-4e1f-b7ff-e5ef72c45496}_maxwidth=0.381 bottomlayer_{dd3d4156-a54d-4e1f-b7ff-e5ef72c45496}_prefwidth=0.381 substack13={7CC4AE65-1EB7-43C1-8FCA-3677EE54F737} toplayer_{7cc4ae65-1eb7-43c1-8fca-3677ee54f737}_minwidth=0.381 toplayer_{7cc4ae65-1eb7-43c1-8fca-3677ee54f737}_maxwidth=0.381 toplayer_{7cc4ae65-1eb7-43c1-8fca-3677ee54f737}_prefwidth=0.381 midlayer1_{7cc4ae65-1eb7-43c1-8fca-3677ee54f737}_minwidth=0.381 midlayer1_{7cc4ae65-1eb7-43c1-8fca-3677ee54f737}_maxwidth=0.381 midlayer1_{7cc4ae65-1eb7-43c1-8fca-3677ee54f737}_prefwidth=0.381 midlayer2_{7cc4ae65-1eb7-43c1-8fca-3677ee54f737}_minwidth=0.381 midlayer2_{7cc4ae65-1eb7-43c1-8fca-3677ee54f737}_maxwidth=0.381 midlayer2_{7cc4ae65-1eb7-43c1-8fca-3677ee54f737}_prefwidth=0.381 midlayer3_{7cc4ae65-1eb7-43c1-8fca-3677ee54f737}_minwidth=0.381 midlayer3_{7cc4ae65-1eb7-43c1-8fca-3677ee54f737}_maxwidth=0.381 midlayer3_{7cc4ae65-1eb7-43c1-8fca-3677ee54f737}_prefwidth=0.381 midlayer4_{7cc4ae65-1eb7-43c1-8fca-3677ee54f737}_minwidth=0.381 midlayer4_{7cc4ae65-1eb7-43c1-8fca-3677ee54f737}_maxwidth=0.381 midlayer4_{7cc4ae65-1eb7-43c1-8fca-3677ee54f737}_prefwidth=0.381 bottomlayer_{7cc4ae65-1eb7-43c1-8fca-3677ee54f737}_minwidth=0.381 bottomlayer_{7cc4ae65-1eb7-43c1-8fca-3677ee54f737}_maxwidth=0.381 bottomlayer_{7cc4ae65-1eb7-43c1-8fca-3677ee54f737}_prefwidth=0.381 substack14={E8C37195-128A-4AA0-B681-9B6788FCEC2F} toplayer_{e8c37195-128a-4aa0-b681-9b6788fcec2f}_minwidth=0.381 toplayer_{e8c37195-128a-4aa0-b681-9b6788fcec2f}_maxwidth=0.381 toplayer_{e8c37195-128a-4aa0-b681-9b6788fcec2f}_prefwidth=0.381 midlayer1_{e8c37195-128a-4aa0-b681-9b6788fcec2f}_minwidth=0.381 midlayer1_{e8c37195-128a-4aa0-b681-9b6788fcec2f}_maxwidth=0.381 midlayer1_{e8c37195-128a-4aa0-b681-9b6788fcec2f}_prefwidth=0.381 midlayer2_{e8c37195-128a-4aa0-b681-9b6788fcec2f}_minwidth=0.381 midlayer2_{e8c37195-128a-4aa0-b681-9b6788fcec2f}_maxwidth=0.381 midlayer2_{e8c37195-128a-4aa0-b681-9b6788fcec2f}_prefwidth=0.381 midlayer3_{e8c37195-128a-4aa0-b681-9b6788fcec2f}_minwidth=0.381 midlayer3_{e8c37195-128a-4aa0-b681-9b6788fcec2f}_maxwidth=0.381 midlayer3_{e8c37195-128a-4aa0-b681-9b6788fcec2f}_prefwidth=0.381 midlayer4_{e8c37195-128a-4aa0-b681-9b6788fcec2f}_minwidth=0.381 midlayer4_{e8c37195-128a-4aa0-b681-9b6788fcec2f}_maxwidth=0.381 midlayer4_{e8c37195-128a-4aa0-b681-9b6788fcec2f}_prefwidth=0.381 bottomlayer_{e8c37195-128a-4aa0-b681-9b6788fcec2f}_minwidth=0.381 bottomlayer_{e8c37195-128a-4aa0-b681-9b6788fcec2f}_maxwidth=0.381 bottomlayer_{e8c37195-128a-4aa0-b681-9b6788fcec2f}_prefwidth=0.381 substack15={92E0C252-34CC-4501-B85F-B111C59C3287} toplayer_{92e0c252-34cc-4501-b85f-b111c59c3287}_minwidth=0.381 toplayer_{92e0c252-34cc-4501-b85f-b111c59c3287}_maxwidth=0.381 toplayer_{92e0c252-34cc-4501-b85f-b111c59c3287}_prefwidth=0.381 midlayer1_{92e0c252-34cc-4501-b85f-b111c59c3287}_minwidth=0.381 midlayer1_{92e0c252-34cc-4501-b85f-b111c59c3287}_maxwidth=0.381 midlayer1_{92e0c252-34cc-4501-b85f-b111c59c3287}_prefwidth=0.381 midlayer2_{92e0c252-34cc-4501-b85f-b111c59c3287}_minwidth=0.381 midlayer2_{92e0c252-34cc-4501-b85f-b111c59c3287}_maxwidth=0.381 midlayer2_{92e0c252-34cc-4501-b85f-b111c59c3287}_prefwidth=0.381 midlayer3_{92e0c252-34cc-4501-b85f-b111c59c3287}_minwidth=0.381 midlayer3_{92e0c252-34cc-4501-b85f-b111c59c3287}_maxwidth=0.381 midlayer3_{92e0c252-34cc-4501-b85f-b111c59c3287}_prefwidth=0.381 midlayer4_{92e0c252-34cc-4501-b85f-b111c59c3287}_minwidth=0.381 midlayer4_{92e0c252-34cc-4501-b85f-b111c59c3287}_maxwidth=0.381 midlayer4_{92e0c252-34cc-4501-b85f-b111c59c3287}_prefwidth=0.381 bottomlayer_{92e0c252-34cc-4501-b85f-b111c59c3287}_minwidth=0.381 bottomlayer_{92e0c252-34cc-4501-b85f-b111c59c3287}_maxwidth=0.381 bottomlayer_{92e0c252-34cc-4501-b85f-b111c59c3287}_prefwidth=0.381 substack16={732F7058-E977-446F-8A06-ECA871B5D75E} toplayer_{732f7058-e977-446f-8a06-eca871b5d75e}_minwidth=0.381 toplayer_{732f7058-e977-446f-8a06-eca871b5d75e}_maxwidth=0.381 toplayer_{732f7058-e977-446f-8a06-eca871b5d75e}_prefwidth=0.381 midlayer1_{732f7058-e977-446f-8a06-eca871b5d75e}_minwidth=0.381 midlayer1_{732f7058-e977-446f-8a06-eca871b5d75e}_maxwidth=0.381 midlayer1_{732f7058-e977-446f-8a06-eca871b5d75e}_prefwidth=0.381 midlayer2_{732f7058-e977-446f-8a06-eca871b5d75e}_minwidth=0.381 midlayer2_{732f7058-e977-446f-8a06-eca871b5d75e}_maxwidth=0.381 midlayer2_{732f7058-e977-446f-8a06-eca871b5d75e}_prefwidth=0.381 midlayer3_{732f7058-e977-446f-8a06-eca871b5d75e}_minwidth=0.381 midlayer3_{732f7058-e977-446f-8a06-eca871b5d75e}_maxwidth=0.381 midlayer3_{732f7058-e977-446f-8a06-eca871b5d75e}_prefwidth=0.381 midlayer4_{732f7058-e977-446f-8a06-eca871b5d75e}_minwidth=0.381 midlayer4_{732f7058-e977-446f-8a06-eca871b5d75e}_maxwidth=0.381 midlayer4_{732f7058-e977-446f-8a06-eca871b5d75e}_prefwidth=0.381 bottomlayer_{732f7058-e977-446f-8a06-eca871b5d75e}_minwidth=0.381 bottomlayer_{732f7058-e977-446f-8a06-eca871b5d75e}_maxwidth=0.381 bottomlayer_{732f7058-e977-446f-8a06-eca871b5d75e}_prefwidth=0.381 substack17={990DA1BC-A1DE-47D8-A675-B5A4E74B5332} toplayer_{990da1bc-a1de-47d8-a675-b5a4e74b5332}_minwidth=0.381 toplayer_{990da1bc-a1de-47d8-a675-b5a4e74b5332}_maxwidth=0.381 toplayer_{990da1bc-a1de-47d8-a675-b5a4e74b5332}_prefwidth=0.381 midlayer1_{990da1bc-a1de-47d8-a675-b5a4e74b5332}_minwidth=0.381 midlayer1_{990da1bc-a1de-47d8-a675-b5a4e74b5332}_maxwidth=0.381 midlayer1_{990da1bc-a1de-47d8-a675-b5a4e74b5332}_prefwidth=0.381 midlayer2_{990da1bc-a1de-47d8-a675-b5a4e74b5332}_minwidth=0.381 midlayer2_{990da1bc-a1de-47d8-a675-b5a4e74b5332}_maxwidth=0.381 midlayer2_{990da1bc-a1de-47d8-a675-b5a4e74b5332}_prefwidth=0.381 midlayer3_{990da1bc-a1de-47d8-a675-b5a4e74b5332}_minwidth=0.381 midlayer3_{990da1bc-a1de-47d8-a675-b5a4e74b5332}_maxwidth=0.381 midlayer3_{990da1bc-a1de-47d8-a675-b5a4e74b5332}_prefwidth=0.381 midlayer4_{990da1bc-a1de-47d8-a675-b5a4e74b5332}_minwidth=0.381 midlayer4_{990da1bc-a1de-47d8-a675-b5a4e74b5332}_maxwidth=0.381 midlayer4_{990da1bc-a1de-47d8-a675-b5a4e74b5332}_prefwidth=0.381 bottomlayer_{990da1bc-a1de-47d8-a675-b5a4e74b5332}_minwidth=0.381 bottomlayer_{990da1bc-a1de-47d8-a675-b5a4e74b5332}_maxwidth=0.381 bottomlayer_{990da1bc-a1de-47d8-a675-b5a4e74b5332}_prefwidth=0.381 maxuncoupledlength=25.4
FabricationTestPointUsage TestPointUsage [All] p1: valid=2 allowmultiple=FALSE
FabricationTestpoint Testpoint [All] p1: side=3 testpointundercomponent=TRUE minsize=1.016 maxsize=2.54 preferedsize=1.524 minholesize=0 maxholesize=1.016 preferedholesize=0.813 testpointgrid=0.025 allowsidetop=TRUE allowsidebottom=TRUE usegrid=TRUE gridtolerance=0
FanoutControl Fanout_LCC [IsLCC] p1: bgadir=Out bgaviamode=Centered fanoutstyle=Auto fanoutdirection=Alternating viagrid=0.025 // Fanout_LCC (Default Rule)
FanoutControl Fanout_BGA [IsBGA] p2: bgadir=Out bgaviamode=Centered fanoutstyle=Auto fanoutdirection=Alternating viagrid=0.025 // Fanout_BGA (Default Rule)
FanoutControl Fanout_Default [All] p4: bgadir=Out bgaviamode=Centered fanoutstyle=Auto fanoutdirection=Alternating viagrid=0.025 // Fanout_Default (Default Rule)
FanoutControl Fanout_Small [(CompPinCount < 5)] p5: bgadir=Out bgaviamode=Centered fanoutstyle=Auto fanoutdirection=OutThenIn viagrid=0.025 // Fanout_Small (Default Rule)
Height [All] p1: minheight=0 maxheight=38.1 prefheight=12.7
HoleSize [All] p1: absolutevalues=TRUE maxlimit=12.7 minlimit=0.2 maxpercent=80.000 minpercent=20.000
HoleToHoleClearance [All] p1: gap=0 allowstackedmicrovias=TRUE
MinimumAnnularRing MinimumAnnularRing_ThermalPadVias [IsVia and InAnyComponent] p1: minimumring=0.15
MinimumAnnularRing [All] p2: minimumring=0.114
MinimumSolderMaskSliver MinimumSolderMaskSliver_Logo [InComponentClass('Logo') vs InComponentClass('Logo')] p1: minsoldermaskwidth=0.003
MinimumSolderMaskSliver [All] p2: minsoldermaskwidth=0.025
PlaneConnect [All] p1: planeconnectstyle=Relief reliefexpansion=0.254 reliefentries=4 reliefconductorwidth=0.254 reliefairgap=0.254
PolygonConnect PolygonConnect_59 [All vs IsNamedPolygon('PGND') Or  IsNamedPolygon('C102_1') Or  IsNamedPolygon('PGND') Or  IsNamedPolygon('F150_2') Or  IsNamedPolygon('C102_1') Or  IsNamedPolygon('F150_1') Or  IsNamedPolygon('C105_2') Or  IsNamedPolygon('ZCD') Or  IsNamedPolygon('C102_1') Or  IsNamedPolygon('C102_1') Or  IsNamedPolygon('PGND') Or  IsNamedPolygon('PGND') Or  IsNamedPolygon('Line') Or  IsNamedPolygon('F150_1') Or  IsNamedPolygon('ZCD') Or  IsNamedPolygon('Line') Or  IsNamedPolygon('Neutral') Or  IsNamedPolygon('F150_2') Or  IsNamedPolygon('Line') Or  IsNamedPolygon('Neutral') Or  IsNamedPolygon('F150_1') Or  IsNamedPolygon('PGND') Or  IsNamedPolygon('SWNODE') Or  IsNamedPolygon('SWNODE') Or  IsNamedPolygon('SWNODE') Or  IsNamedPolygon('PGND') Or  IsNamedPolygon('Line') Or  IsNamedPolygon('Vbulk1') Or  IsNamedPolygon('C105_2') Or  IsNamedPolygon('PGND') Or  IsNamedPolygon('C105_2') Or  IsNamedPolygon('PGND') Or  IsNamedPolygon('C105_1') Or  IsNamedPolygon('PGND') Or  IsNamedPolygon('Vbulk') Or  IsNamedPolygon('Vbulk') Or  IsNamedPolygon('F150_1') Or  IsNamedPolygon('Vbulk') Or  IsNamedPolygon('PGND') Or  IsNamedPolygon('C105_1') Or  IsNamedPolygon('Neutral') Or  IsNamedPolygon('Neutral') Or  IsNamedPolygon('SWNODE') Or  IsNamedPolygon('C102_1') Or  IsNamedPolygon('F150_2') Or  IsNamedPolygon('C105_1') Or  IsNamedPolygon('Line') Or  IsNamedPolygon('F150_2') Or  IsNamedPolygon('F150_2') Or  IsNamedPolygon('F150_1') Or  IsNamedPolygon('C105_1') Or  IsNamedPolygon('Vbulk1') Or  IsNamedPolygon('PGND') Or  IsNamedPolygon('C105_2') Or  IsNamedPolygon('F150_1') Or  IsNamedPolygon('C105_1') Or  IsNamedPolygon('F150_2') Or  IsNamedPolygon('C102_1') Or  IsNamedPolygon('PGND') Or  IsNamedPolygon('VBB') Or  IsNamedPolygon('12Vp') Or  IsNamedPolygon('J102_1') Or  IsNamedPolygon('J102_1') Or  IsNamedPolygon('Neutral') Or  IsNamedPolygon('Neutral') Or  IsNamedPolygon('PGND') Or  IsNamedPolygon('VBB') Or  IsNamedPolygon('Vbulk') Or  IsNamedPolygon('VBB') Or  IsNamedPolygon('C105_2') Or  IsNamedPolygon('ZCD') Or  IsNamedPolygon('C105_2') Or  IsNamedPolygon('ZCD') Or  IsNamedPolygon('Vbulk') Or  IsNamedPolygon('ZCD') Or  IsNamedPolygon('5Vp') Or  IsNamedPolygon('J102_1') Or  IsNamedPolygon('SWNODE') Or  IsNamedPolygon('PGND') Or  IsNamedPolygon('ZCD') Or  IsNamedPolygon('D106_1') Or  IsNamedPolygon('VBB') Or  IsNamedPolygon('J102_1') Or  IsNamedPolygon('J102_1') Or  IsNamedPolygon('PGND') Or  IsNamedPolygon('VBB') Or  IsNamedPolygon('D106_1') Or  IsNamedPolygon('PGND') Or  IsNamedPolygon('SWNODE') Or  IsNamedPolygon('ZCD') Or  IsNamedPolygon('PGND') Or  IsNamedPolygon('Vbulk1') Or  IsNamedPolygon('ZCD') Or  IsNamedPolygon('Line') Or  IsNamedPolygon('Vbulk') Or  IsNamedPolygon('PGND') Or  IsNamedPolygon('PGND') Or  IsNamedPolygon('VBB') Or  IsNamedPolygon('PGND') Or  IsNamedPolygon('C105_1') Or  IsNamedPolygon('VBB') Or  IsNamedPolygon('ZCD') Or  IsNamedPolygon('Neutral') Or  IsNamedPolygon('ZCD') Or  IsNamedPolygon('PE') Or  IsNamedPolygon('J102_1') Or  IsNamedPolygon('Vbulk') Or  IsNamedPolygon('Vbulk1')] p1: connectstyle=Direct reliefconductorwidth=0.254 reliefentries=4 polygonreliefangle="90 Angle" airgapwidth=0.254
PolygonConnect PolygonConnect_58 [All vs IsNamedPolygon('C105_1') Or  IsNamedPolygon('12Vp') Or  IsNamedPolygon('Neutral') Or  IsNamedPolygon('C105_2') Or  IsNamedPolygon('ZCD') Or  IsNamedPolygon('C105_1') Or  IsNamedPolygon('VBB') Or  IsNamedPolygon('PGND') Or  IsNamedPolygon('F150_2') Or  IsNamedPolygon('SWNODE') Or  IsNamedPolygon('PGND') Or  IsNamedPolygon('PGND') Or  IsNamedPolygon('J102_1') Or  IsNamedPolygon('D106_1') Or  IsNamedPolygon('PGND') Or  IsNamedPolygon('C105_2') Or  IsNamedPolygon('SWNODE') Or  IsNamedPolygon('Vbulk') Or  IsNamedPolygon('PGND') Or  IsNamedPolygon('PGND') Or  IsNamedPolygon('PGND') Or  IsNamedPolygon('PGND') Or  IsNamedPolygon('Vbulk') Or  IsNamedPolygon('PGND') Or  IsNamedPolygon('PGND') Or  IsNamedPolygon('D106_1') Or  IsNamedPolygon('Neutral') Or  IsNamedPolygon('PGND') Or  IsNamedPolygon('C105_2') Or  IsNamedPolygon('Vbulk') Or  IsNamedPolygon('SWNODE') Or  IsNamedPolygon('VBB') Or  IsNamedPolygon('J102_1') Or  IsNamedPolygon('VBB') Or  IsNamedPolygon('PGND') Or  IsNamedPolygon('5Vp') Or  IsNamedPolygon('SWNODE') Or  IsNamedPolygon('C105_1') Or  IsNamedPolygon('VBB') Or  IsNamedPolygon('SWNODE') Or  IsNamedPolygon('ZCD') Or  IsNamedPolygon('Vbulk') Or  IsNamedPolygon('Line') Or  IsNamedPolygon('Vbulk1') Or  IsNamedPolygon('PGND') Or  IsNamedPolygon('ZCD') Or  IsNamedPolygon('VBB') Or  IsNamedPolygon('PGND') Or  IsNamedPolygon('ZCD') Or  IsNamedPolygon('Vbulk1') Or  IsNamedPolygon('Neutral') Or  IsNamedPolygon('F150_2') Or  IsNamedPolygon('F150_2') Or  IsNamedPolygon('PGND') Or  IsNamedPolygon('Neutral') Or  IsNamedPolygon('C102_1') Or  IsNamedPolygon('C105_1') Or  IsNamedPolygon('Line') Or  IsNamedPolygon('J102_1') Or  IsNamedPolygon('Neutral') Or  IsNamedPolygon('Neutral') Or  IsNamedPolygon('SWNODE') Or  IsNamedPolygon('ZCD') Or  IsNamedPolygon('J102_1') Or  IsNamedPolygon('J102_1') Or  IsNamedPolygon('PGND') Or  IsNamedPolygon('ZCD') Or  IsNamedPolygon('Vbulk') Or  IsNamedPolygon('Line') Or  IsNamedPolygon('VBB') Or  IsNamedPolygon('Vbulk') Or  IsNamedPolygon('VBB') Or  IsNamedPolygon('Line') Or  IsNamedPolygon('C105_1') Or  IsNamedPolygon('ZCD') Or  IsNamedPolygon('C105_2') Or  IsNamedPolygon('Line') Or  IsNamedPolygon('C105_2') Or  IsNamedPolygon('PGND') Or  IsNamedPolygon('PE') Or  IsNamedPolygon('Neutral') Or  IsNamedPolygon('F150_2') Or  IsNamedPolygon('ZCD') Or  IsNamedPolygon('F150_2') Or  IsNamedPolygon('F150_2') Or  IsNamedPolygon('ZCD') Or  IsNamedPolygon('PGND') Or  IsNamedPolygon('PGND') Or  IsNamedPolygon('Vbulk1') Or  IsNamedPolygon('Line') Or  IsNamedPolygon('ZCD') Or  IsNamedPolygon('C105_1') Or  IsNamedPolygon('J102_1') Or  IsNamedPolygon('Vbulk1') Or  IsNamedPolygon('Vbulk') Or  IsNamedPolygon('C105_2') Or  IsNamedPolygon('PGND')] p2: connectstyle=Direct reliefconductorwidth=0.254 reliefentries=4 polygonreliefangle="90 Angle" airgapwidth=0.254
PolygonConnect PolygonConnect_57 [All vs IsNamedPolygon('PGND') Or  IsNamedPolygon('C105_2') Or  IsNamedPolygon('VBB') Or  IsNamedPolygon('5Vp') Or  IsNamedPolygon('ZCD') Or  IsNamedPolygon('J102_1') Or  IsNamedPolygon('PGND') Or  IsNamedPolygon('PGND') Or  IsNamedPolygon('PGND') Or  IsNamedPolygon('PE') Or  IsNamedPolygon('VBB') Or  IsNamedPolygon('VBB') Or  IsNamedPolygon('ZCD') Or  IsNamedPolygon('ZCD') Or  IsNamedPolygon('Line') Or  IsNamedPolygon('PGND') Or  IsNamedPolygon('C102_1') Or  IsNamedPolygon('VBB') Or  IsNamedPolygon('J102_1') Or  IsNamedPolygon('Vbulk') Or  IsNamedPolygon('PGND') Or  IsNamedPolygon('Neutral') Or  IsNamedPolygon('Vbulk') Or  IsNamedPolygon('ZCD') Or  IsNamedPolygon('J102_1') Or  IsNamedPolygon('PGND') Or  IsNamedPolygon('ZCD') Or  IsNamedPolygon('J102_1') Or  IsNamedPolygon('VBB') Or  IsNamedPolygon('Neutral') Or  IsNamedPolygon('PGND') Or  IsNamedPolygon('PGND') Or  IsNamedPolygon('12Vp') Or  IsNamedPolygon('Vbulk') Or  IsNamedPolygon('PGND') Or  IsNamedPolygon('Vbulk') Or  IsNamedPolygon('J102_1') Or  IsNamedPolygon('PGND') Or  IsNamedPolygon('D106_1') Or  IsNamedPolygon('PGND') Or  IsNamedPolygon('Vbulk1') Or  IsNamedPolygon('PGND') Or  IsNamedPolygon('C105_2') Or  IsNamedPolygon('Vbulk') Or  IsNamedPolygon('Neutral') Or  IsNamedPolygon('Vbulk1') Or  IsNamedPolygon('PGND') Or  IsNamedPolygon('PGND') Or  IsNamedPolygon('J102_1') Or  IsNamedPolygon('SWNODE') Or  IsNamedPolygon('Vbulk1') Or  IsNamedPolygon('C105_2') Or  IsNamedPolygon('VBB') Or  IsNamedPolygon('VBB') Or  IsNamedPolygon('ZCD') Or  IsNamedPolygon('SWNODE') Or  IsNamedPolygon('Vbulk') Or  IsNamedPolygon('PGND') Or  IsNamedPolygon('Vbulk') Or  IsNamedPolygon('C105_1') Or  IsNamedPolygon('PGND') Or  IsNamedPolygon('PGND') Or  IsNamedPolygon('ZCD') Or  IsNamedPolygon('C105_2') Or  IsNamedPolygon('D106_1') Or  IsNamedPolygon('PGND') Or  IsNamedPolygon('C105_2') Or  IsNamedPolygon('C105_2') Or  IsNamedPolygon('ZCD') Or  IsNamedPolygon('PGND')] p3: connectstyle=Direct reliefconductorwidth=0.254 reliefentries=4 polygonreliefangle="90 Angle" airgapwidth=0.254
PolygonConnect PolygonConnect_56 [All vs IsNamedPolygon('PGND') Or  IsNamedPolygon('C105_2') Or  IsNamedPolygon('VBB') Or  IsNamedPolygon('5Vp') Or  IsNamedPolygon('ZCD') Or  IsNamedPolygon('J102_1') Or  IsNamedPolygon('PGND') Or  IsNamedPolygon('PGND') Or  IsNamedPolygon('PGND') Or  IsNamedPolygon('PE') Or  IsNamedPolygon('VBB') Or  IsNamedPolygon('VBB') Or  IsNamedPolygon('ZCD') Or  IsNamedPolygon('ZCD') Or  IsNamedPolygon('Line') Or  IsNamedPolygon('PGND') Or  IsNamedPolygon('C102_1') Or  IsNamedPolygon('VBB') Or  IsNamedPolygon('J102_1') Or  IsNamedPolygon('Vbulk') Or  IsNamedPolygon('PGND') Or  IsNamedPolygon('Neutral') Or  IsNamedPolygon('Vbulk') Or  IsNamedPolygon('ZCD') Or  IsNamedPolygon('J102_1') Or  IsNamedPolygon('PGND') Or  IsNamedPolygon('ZCD') Or  IsNamedPolygon('J102_1') Or  IsNamedPolygon('VBB') Or  IsNamedPolygon('Neutral') Or  IsNamedPolygon('PGND') Or  IsNamedPolygon('PGND') Or  IsNamedPolygon('12Vp') Or  IsNamedPolygon('Vbulk') Or  IsNamedPolygon('PGND') Or  IsNamedPolygon('Vbulk') Or  IsNamedPolygon('J102_1') Or  IsNamedPolygon('PGND') Or  IsNamedPolygon('D106_1') Or  IsNamedPolygon('PGND') Or  IsNamedPolygon('Vbulk1') Or  IsNamedPolygon('PGND') Or  IsNamedPolygon('C105_2') Or  IsNamedPolygon('Vbulk') Or  IsNamedPolygon('Neutral') Or  IsNamedPolygon('Vbulk1') Or  IsNamedPolygon('PGND') Or  IsNamedPolygon('PGND') Or  IsNamedPolygon('J102_1') Or  IsNamedPolygon('SWNODE') Or  IsNamedPolygon('Vbulk1') Or  IsNamedPolygon('C105_2') Or  IsNamedPolygon('VBB') Or  IsNamedPolygon('VBB') Or  IsNamedPolygon('ZCD') Or  IsNamedPolygon('SWNODE') Or  IsNamedPolygon('Vbulk') Or  IsNamedPolygon('PGND') Or  IsNamedPolygon('Vbulk') Or  IsNamedPolygon('C105_1') Or  IsNamedPolygon('PGND') Or  IsNamedPolygon('PGND') Or  IsNamedPolygon('ZCD') Or  IsNamedPolygon('C105_2') Or  IsNamedPolygon('D106_1') Or  IsNamedPolygon('PGND') Or  IsNamedPolygon('C105_2') Or  IsNamedPolygon('C105_2') Or  IsNamedPolygon('ZCD') Or  IsNamedPolygon('PGND')] p4: thpad.connectstyle=Direct thpad.reliefconductorwidth=0.254 thpad.reliefentries=4 thpad.polygonreliefangle="90 Angle" thpad.airgapwidth=0.254 smdpad.connectstyle=Relief smdpad.reliefconductorwidth=0.254 smdpad.reliefentries=4 smdpad.polygonreliefangle="90 Angle" smdpad.airgapwidth=0.254 via.connectstyle=Relief via.reliefconductorwidth=0.254 via.reliefentries=4 via.polygonreliefangle="90 Angle" via.airgapwidth=0.254
PolygonConnect PolygonConnect_55 [All vs IsNamedPolygon('SWNODE') Or  IsNamedPolygon('ZCD') Or  IsNamedPolygon('PGND') Or  IsNamedPolygon('PGND') Or  IsNamedPolygon('PGND') Or  IsNamedPolygon('PGND') Or  IsNamedPolygon('PGND') Or  IsNamedPolygon('PGND') Or  IsNamedPolygon('Vbulk') Or  IsNamedPolygon('D106_1') Or  IsNamedPolygon('Vbulk') Or  IsNamedPolygon('D106_1') Or  IsNamedPolygon('VBB') Or  IsNamedPolygon('PGND') Or  IsNamedPolygon('PGND') Or  IsNamedPolygon('Vbulk') Or  IsNamedPolygon('VBB') Or  IsNamedPolygon('ZCD') Or  IsNamedPolygon('Vbulk') Or  IsNamedPolygon('ZCD') Or  IsNamedPolygon('VBB') Or  IsNamedPolygon('VBB') Or  IsNamedPolygon('VBB') Or  IsNamedPolygon('VBB') Or  IsNamedPolygon('VBB') Or  IsNamedPolygon('ZCD') Or  IsNamedPolygon('C102_1') Or  IsNamedPolygon('12Vp') Or  IsNamedPolygon('C105_1') Or  IsNamedPolygon('PGND') Or  IsNamedPolygon('SWNODE') Or  IsNamedPolygon('Vbulk') Or  IsNamedPolygon('Vbulk1') Or  IsNamedPolygon('Vbulk1') Or  IsNamedPolygon('Neutral') Or  IsNamedPolygon('ZCD') Or  IsNamedPolygon('Neutral') Or  IsNamedPolygon('ZCD') Or  IsNamedPolygon('5Vp') Or  IsNamedPolygon('Neutral') Or  IsNamedPolygon('ZCD') Or  IsNamedPolygon('Line') Or  IsNamedPolygon('ZCD')] p5: connectstyle=Direct reliefconductorwidth=0.254 reliefentries=4 polygonreliefangle="90 Angle" airgapwidth=0.254
PolygonConnect PolygonConnect_54 [All vs IsNamedPolygon('12Vp') Or  IsNamedPolygon('SWNODE') Or  IsNamedPolygon('D403_2') Or  IsNamedPolygon('D403_2') Or  IsNamedPolygon('PGND') Or  IsNamedPolygon('BOTTOM_LAYER_NETC106_2_P030') Or  IsNamedPolygon('C102_1') Or  IsNamedPolygon('SGND') Or  IsNamedPolygon('TOP_LAYER_54V1_P046') Or  IsNamedPolygon('TOP_LAYER_54V2_P048') Or  IsNamedPolygon('TOP_LAYER_54V2_P048') Or  IsNamedPolygon('C108_1') Or  IsNamedPolygon('C108_1') Or  IsNamedPolygon('C108_1') Or  IsNamedPolygon('C108_1') Or  IsNamedPolygon('C108_1') Or  IsNamedPolygon('C108_1') Or  IsNamedPolygon('PGND') Or  IsNamedPolygon('ZCD') Or  IsNamedPolygon('Line') Or  IsNamedPolygon('5Vp') Or  IsNamedPolygon('12Vp') Or  IsNamedPolygon('T200_4') Or  IsNamedPolygon('T200_6') Or  IsNamedPolygon('SWNODE3') Or  IsNamedPolygon('T200_4') Or  IsNamedPolygon('T200_6') Or  IsNamedPolygon('SWNODE4') Or  IsNamedPolygon('VSR') Or  IsNamedPolygon('TOP_LAYER_IOUT_SNS_P092') Or  IsNamedPolygon('SIGNAL_LAYER_2_VBB_P094') Or  IsNamedPolygon('Vbulk1') Or  IsNamedPolygon('TOP_LAYER_VBULK_P104') Or  IsNamedPolygon('SIGNAL_LAYER_1_VBULK1_P106') Or  IsNamedPolygon('Line') Or  IsNamedPolygon('Line') Or  IsNamedPolygon('D404_2') Or  IsNamedPolygon('Vbulk') Or  IsNamedPolygon('D400_2') Or  IsNamedPolygon('SGND') Or  IsNamedPolygon('PGND') Or  IsNamedPolygon('TOP_LAYER_12VS_P126') Or  IsNamedPolygon('LEG3_HS_DRV') Or  IsNamedPolygon('LEG4_LS_DRV') Or  IsNamedPolygon('LEG4_HS_DRV') Or  IsNamedPolygon('SWNODE4') Or  IsNamedPolygon('SWNODE3') Or  IsNamedPolygon('T200_6') Or  IsNamedPolygon('T200_4') Or  IsNamedPolygon('VBB') Or  IsNamedPolygon('5Vs') Or  IsNamedPolygon('SGND') Or  IsNamedPolygon('Iout_SNS') Or  IsNamedPolygon('SGND') Or  IsNamedPolygon('SWNODE3') Or  IsNamedPolygon('SWNODE3') Or  IsNamedPolygon('SWNODE3') Or  IsNamedPolygon('SWNODE3') Or  IsNamedPolygon('SGND') Or  IsNamedPolygon('SGND') Or  IsNamedPolygon('SGND') Or  IsNamedPolygon('SWNODE4') Or  IsNamedPolygon('SWNODE4') Or  IsNamedPolygon('SWNODE4') Or  IsNamedPolygon('VSR') Or  IsNamedPolygon('SWNODE3') Or  IsNamedPolygon('SGND') Or  IsNamedPolygon('SGND') Or  IsNamedPolygon('SGND') Or  IsNamedPolygon('SGND') Or  IsNamedPolygon('SGND') Or  IsNamedPolygon('SGND') Or  IsNamedPolygon('54V1') Or  IsNamedPolygon('SGND') Or  IsNamedPolygon('VSR') Or  IsNamedPolygon('C102_1') Or  IsNamedPolygon('C102_1') Or  IsNamedPolygon('C102_1') Or  IsNamedPolygon('C102_1') Or  IsNamedPolygon('C102_1') Or  IsNamedPolygon('ZCD') Or  IsNamedPolygon('PGND') Or  IsNamedPolygon('PGND') Or  IsNamedPolygon('Vbulk1') Or  IsNamedPolygon('Vbulk') Or  IsNamedPolygon('Vbulk1') Or  IsNamedPolygon('Vbulk1') Or  IsNamedPolygon('ZCD') Or  IsNamedPolygon('Neutral') Or  IsNamedPolygon('Neutral') Or  IsNamedPolygon('C106_2') Or  IsNamedPolygon('C106_2') Or  IsNamedPolygon('C106_2') Or  IsNamedPolygon('SWNODE') Or  IsNamedPolygon('Vbulk1') Or  IsNamedPolygon('Earth1') Or  IsNamedPolygon('Earth1') Or  IsNamedPolygon('Earth1') Or  IsNamedPolygon('Earth1') Or  IsNamedPolygon('Earth1') Or  IsNamedPolygon('Earth1') Or  IsNamedPolygon('ZCD') Or  IsNamedPolygon('VBB') Or  IsNamedPolygon('PGND') Or  IsNamedPolygon('D106_1') Or  IsNamedPolygon('PGND') Or  IsNamedPolygon('PGND') Or  IsNamedPolygon('D106_1') Or  IsNamedPolygon('Vbulk') Or  IsNamedPolygon('D106_1') Or  IsNamedPolygon('PGND') Or  IsNamedPolygon('VBB') Or  IsNamedPolygon('VBB') Or  IsNamedPolygon('PGND') Or  IsNamedPolygon('PGND') Or  IsNamedPolygon('PGND') Or  IsNamedPolygon('PGND') Or  IsNamedPolygon('PGND') Or  IsNamedPolygon('ZCD') Or  IsNamedPolygon('ZCD') Or  IsNamedPolygon('C412_2') Or  IsNamedPolygon('VBB') Or  IsNamedPolygon('PGND') Or  IsNamedPolygon('PGND') Or  IsNamedPolygon('PGND') Or  IsNamedPolygon('PGND') Or  IsNamedPolygon('PGND') Or  IsNamedPolygon('PGND') Or  IsNamedPolygon('PGND') Or  IsNamedPolygon('Vbulk') Or  IsNamedPolygon('D404_2') Or  IsNamedPolygon('PGND') Or  IsNamedPolygon('Iout_SNS') Or  IsNamedPolygon('54V2') Or  IsNamedPolygon('54V2') Or  IsNamedPolygon('54V2') Or  IsNamedPolygon('54V2') Or  IsNamedPolygon('VSR') Or  IsNamedPolygon('VSR') Or  IsNamedPolygon('Iout_SNS') Or  IsNamedPolygon('SGND') Or  IsNamedPolygon('SGND') Or  IsNamedPolygon('BOTTOM_LAYER_54V1_P154') Or  IsNamedPolygon('ZCD') Or  IsNamedPolygon('PGND')] p6: connectstyle=Direct reliefconductorwidth=0.254 reliefentries=4 polygonreliefangle="90 Angle" airgapwidth=0.254
PolygonConnect PolygonConnect_53 [All vs IsNamedPolygon('BOTTOM_LAYER_54V1_P350')] p7: connectstyle=Direct reliefconductorwidth=0.254 reliefentries=4 polygonreliefangle="90 Angle" airgapwidth=0.254
PolygonConnect PolygonConnect_52 [All vs IsNamedPolygon('TOP_LAYER_54V1_P046')] p8: connectstyle=Direct reliefconductorwidth=0.254 reliefentries=4 polygonreliefangle="90 Angle" airgapwidth=0.254
PolygonConnect PolygonConnect_51 [All vs IsNamedPolygon('SIGNAL_LAYER_1_VBULK1_P106')] p9: connectstyle=Direct reliefconductorwidth=0.254 reliefentries=4 polygonreliefangle="90 Angle" airgapwidth=0.254
PolygonConnect PolygonConnect_50 [All vs IsNamedPolygon('BOTTOM_LAYER_54V1_P128')] p10: connectstyle=Direct reliefconductorwidth=0.254 reliefentries=4 polygonreliefangle="90 Angle" airgapwidth=0.254
PolygonConnect PolygonConnect_49 [All vs IsNamedPolygon('BOTTOM_LAYER_54V1_P128')] p11: connectstyle=Direct reliefconductorwidth=0.254 reliefentries=4 polygonreliefangle="90 Angle" airgapwidth=0.254
PolygonConnect PolygonConnect_48 [All vs IsNamedPolygon('BOTTOM_LAYER_54V1_P128')] p12: connectstyle=Direct reliefconductorwidth=0.254 reliefentries=4 polygonreliefangle="90 Angle" airgapwidth=0.254
PolygonConnect PolygonConnect_47 [All vs IsNamedPolygon('BOTTOM_LAYER_54V1_P128')] p13: connectstyle=Direct reliefconductorwidth=0.254 reliefentries=4 polygonreliefangle="90 Angle" airgapwidth=0.254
